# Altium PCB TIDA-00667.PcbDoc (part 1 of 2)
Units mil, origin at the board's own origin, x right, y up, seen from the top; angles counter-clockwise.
Board outline 4000 x 4000 mil, 6 copper layers (Top, Inner Layer 2, Inner Layer 3, Inner Layer 4, Inner Layer 5, Bottom), stack 58.1 mil thick; 114 components, 88 nets, 384 pads, 631 vias.
Unrouted connection lines stored in the file: 538.
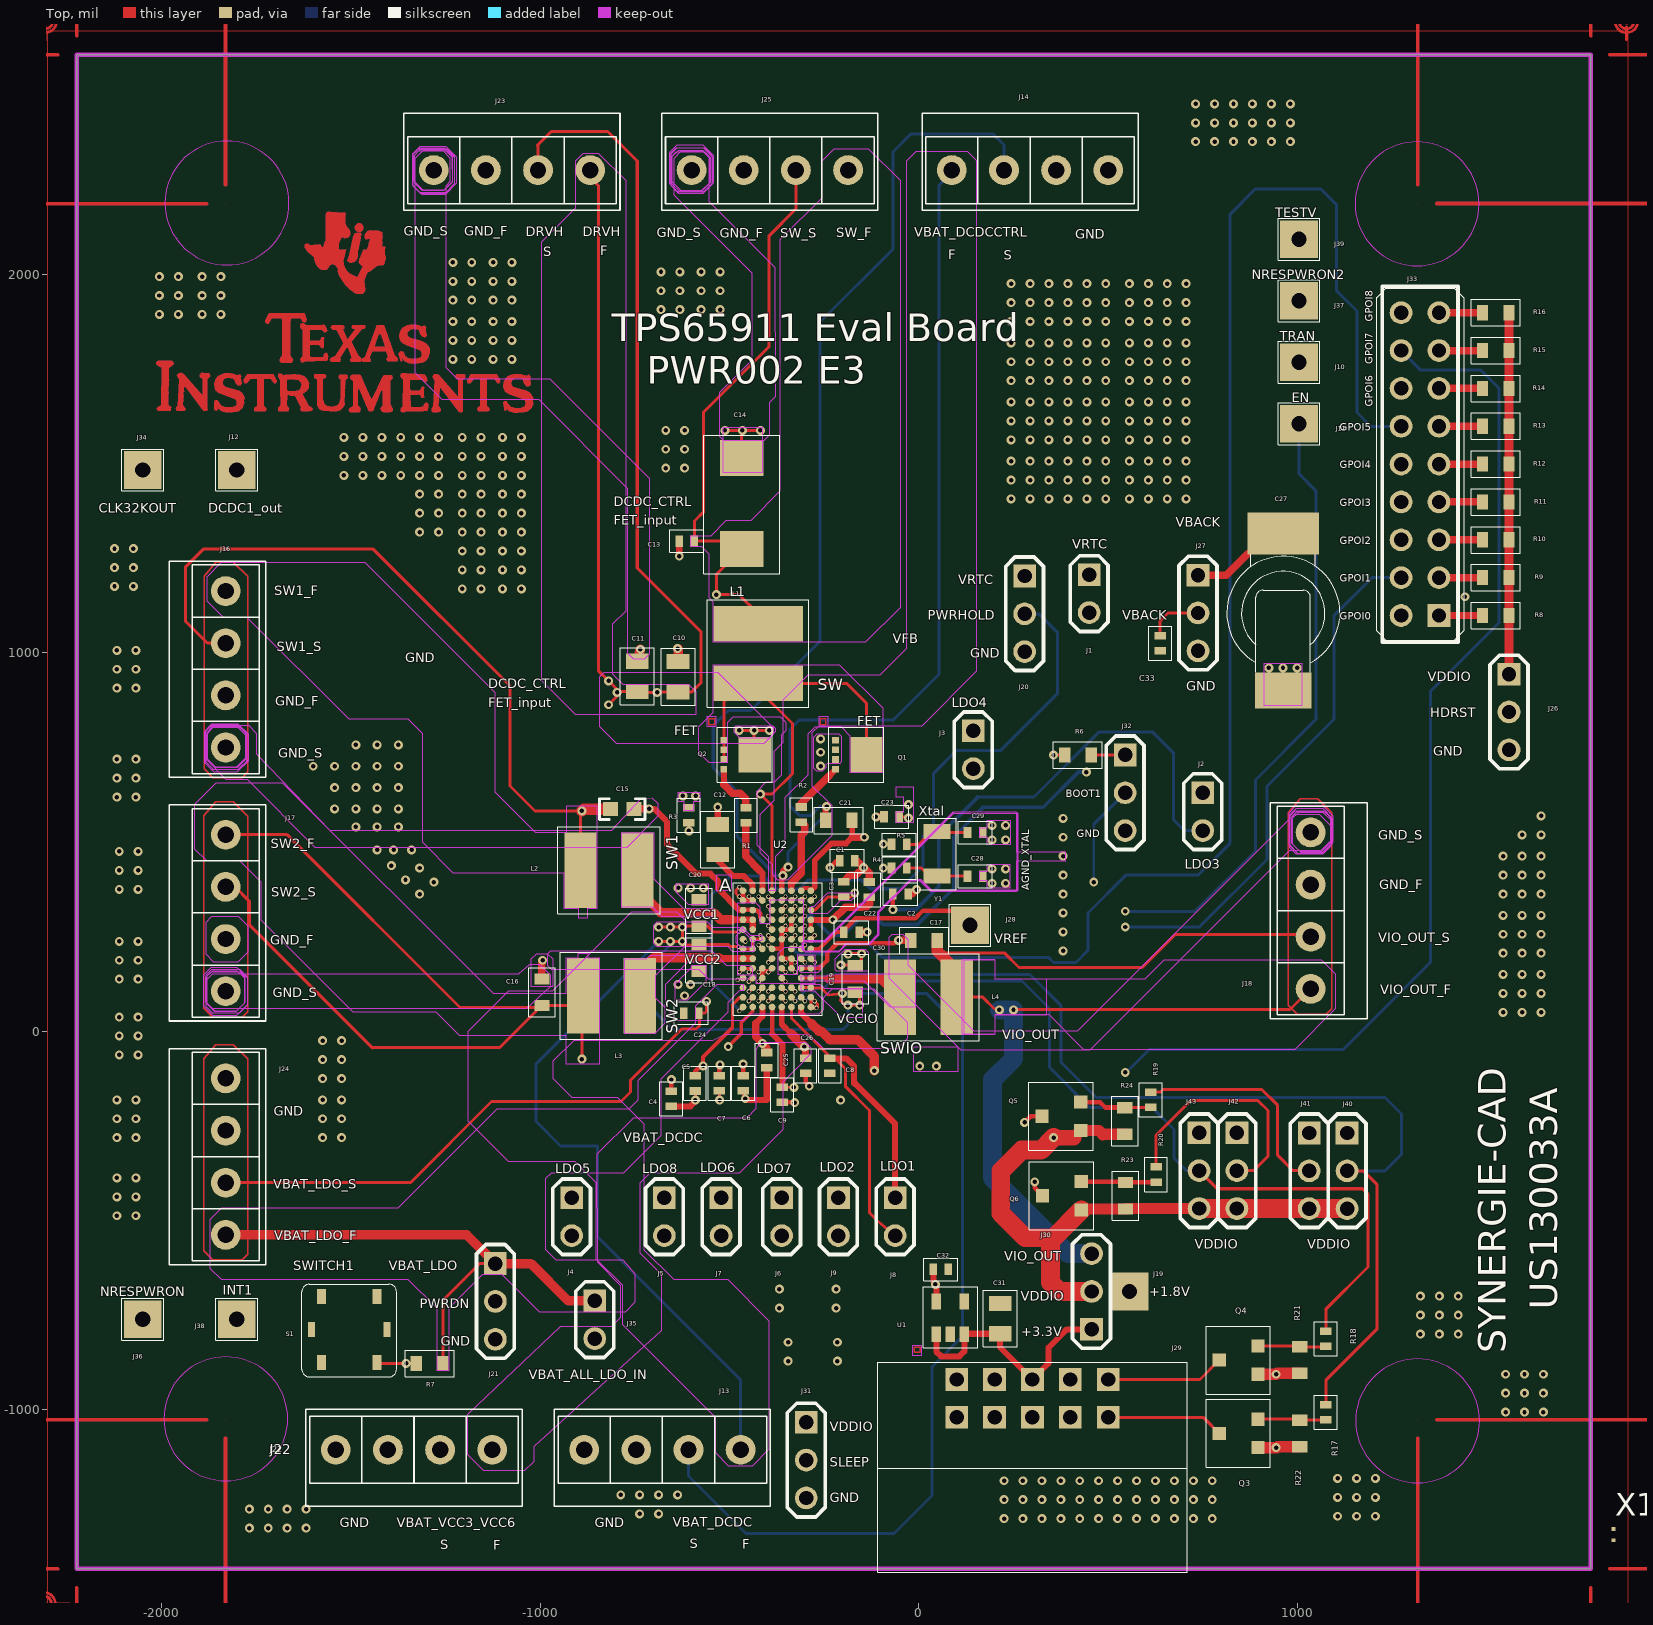
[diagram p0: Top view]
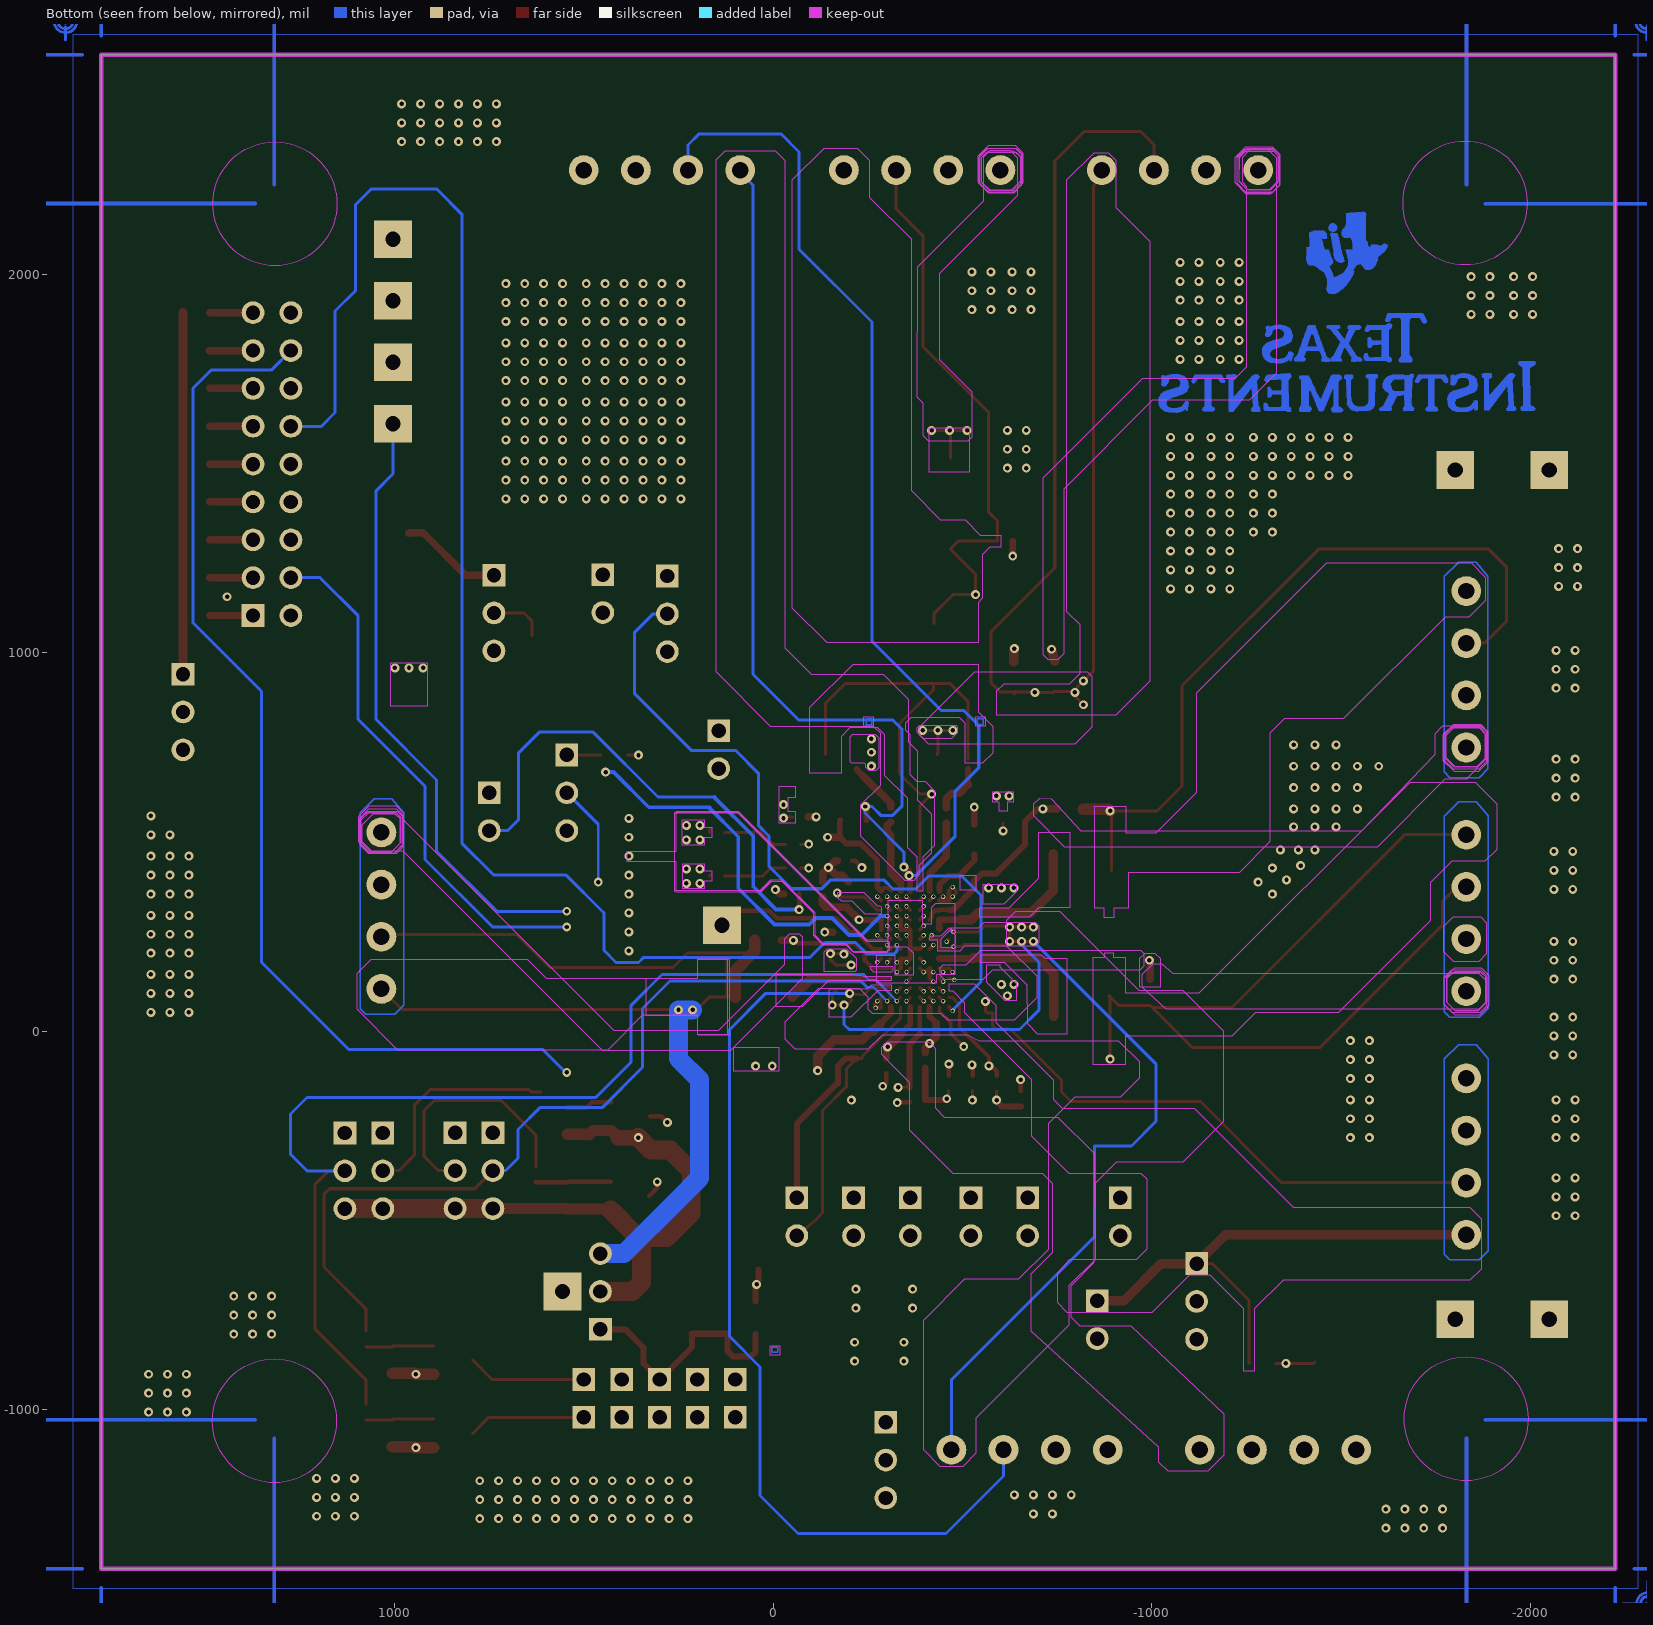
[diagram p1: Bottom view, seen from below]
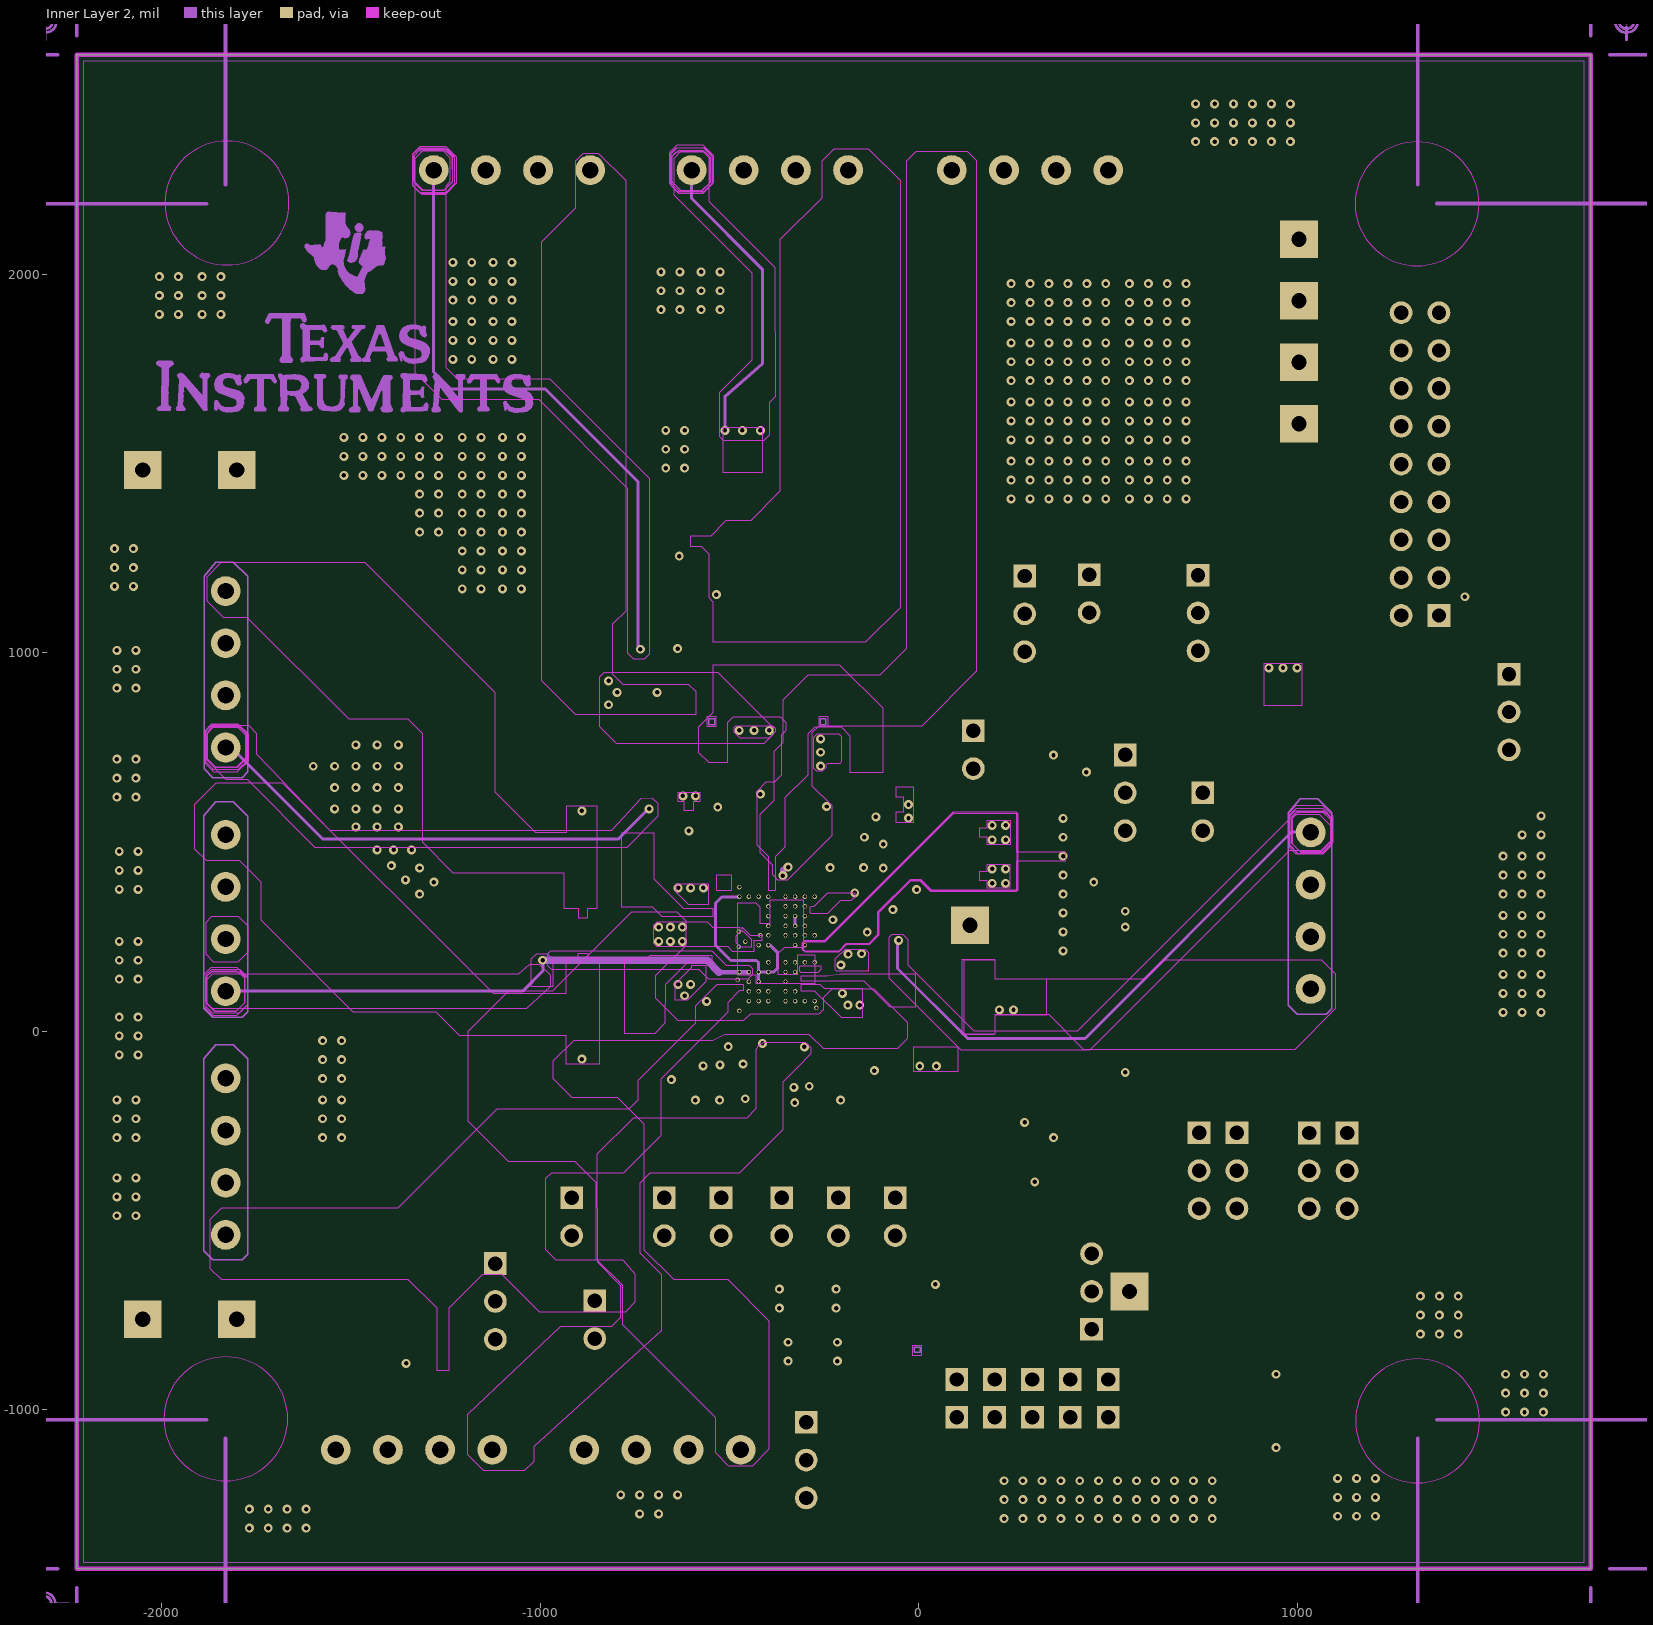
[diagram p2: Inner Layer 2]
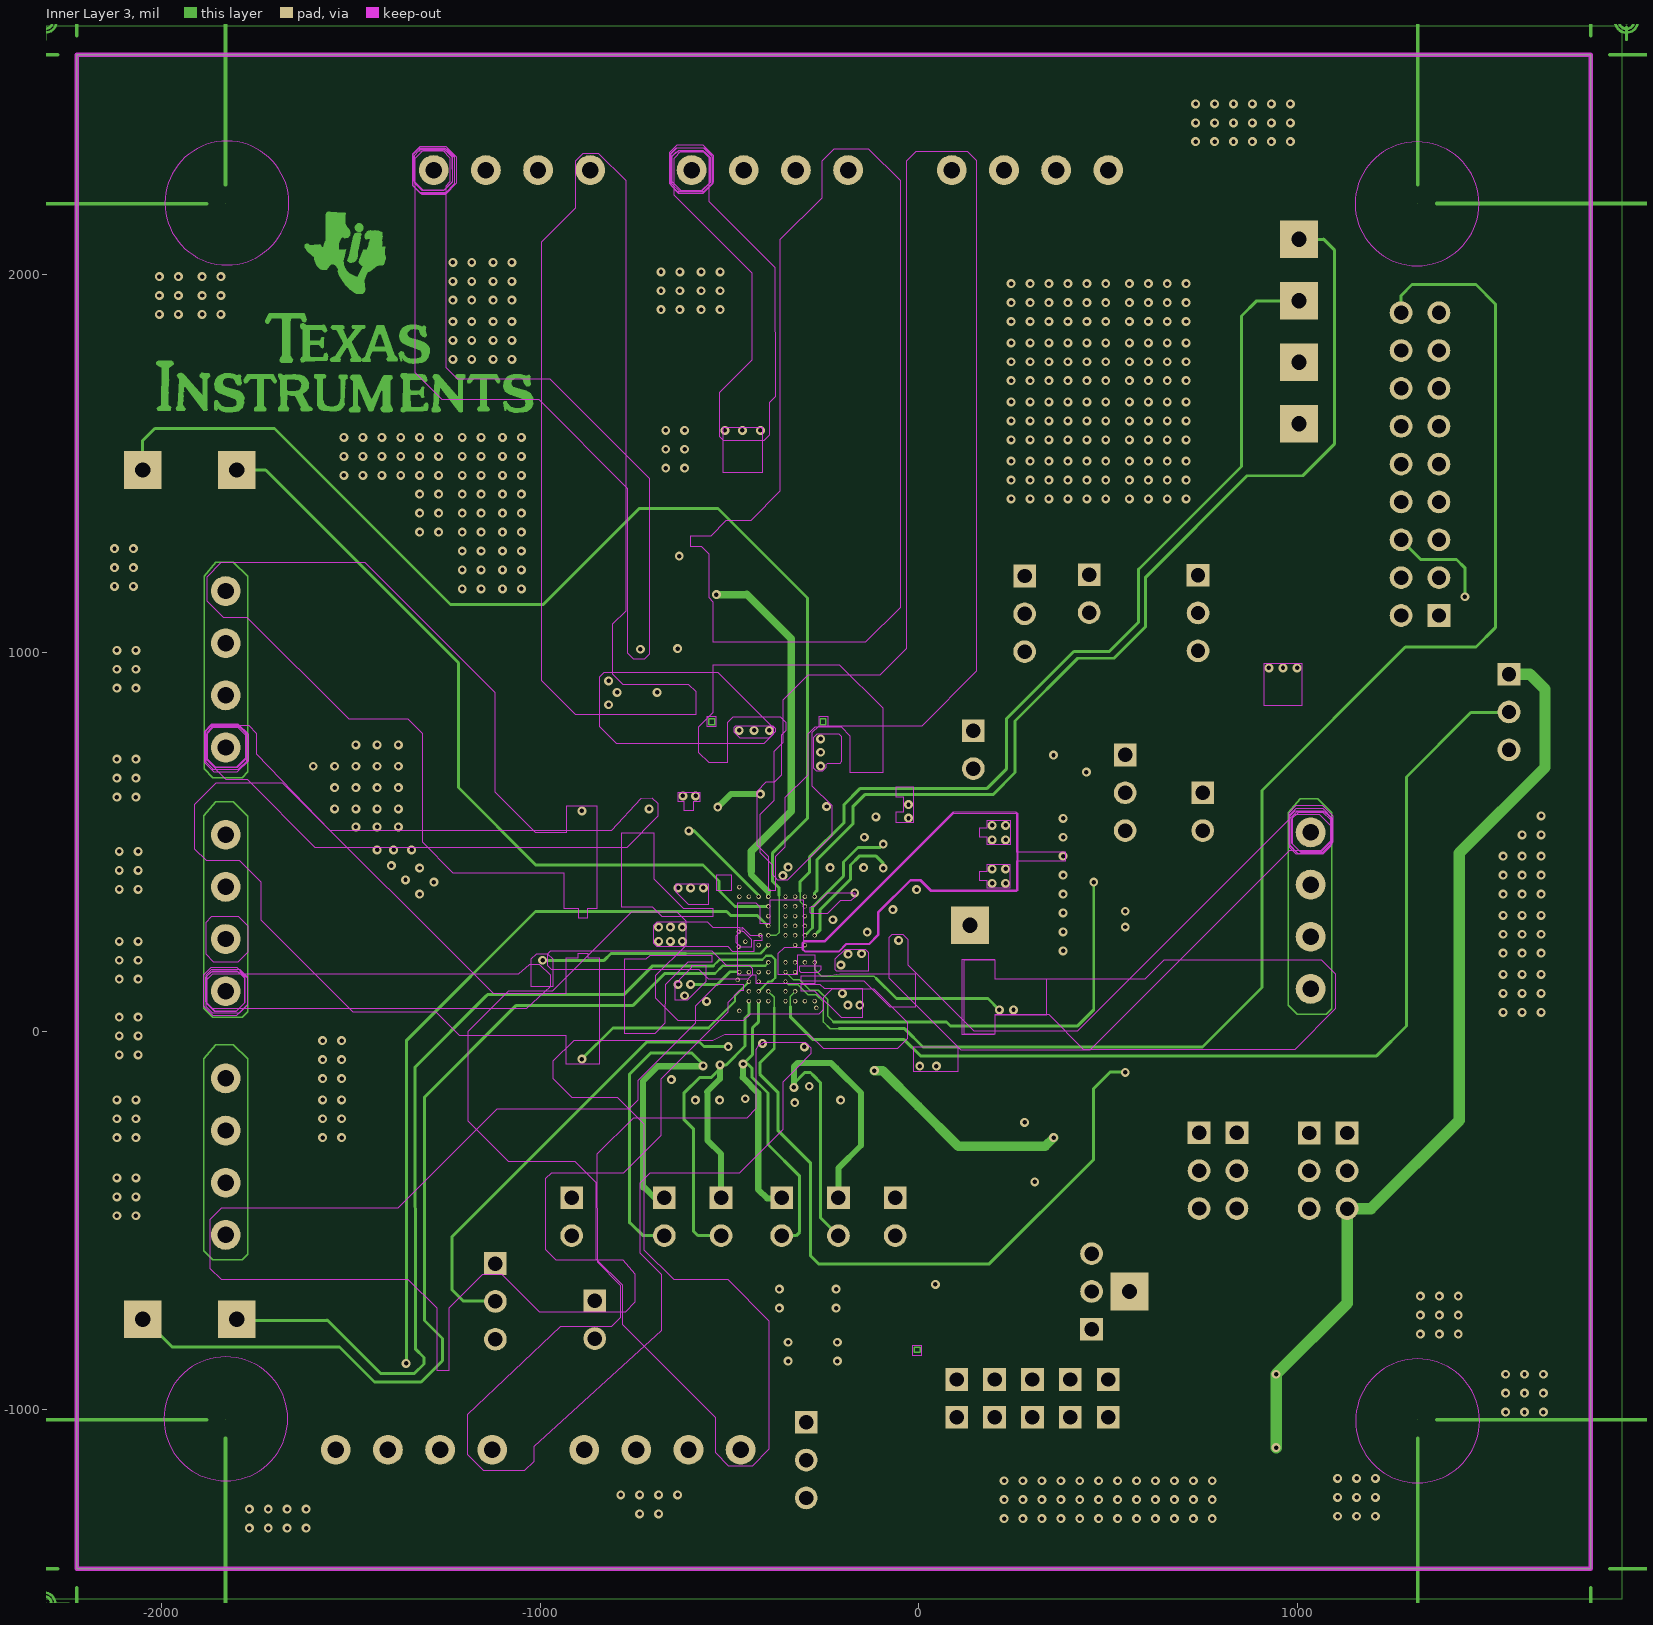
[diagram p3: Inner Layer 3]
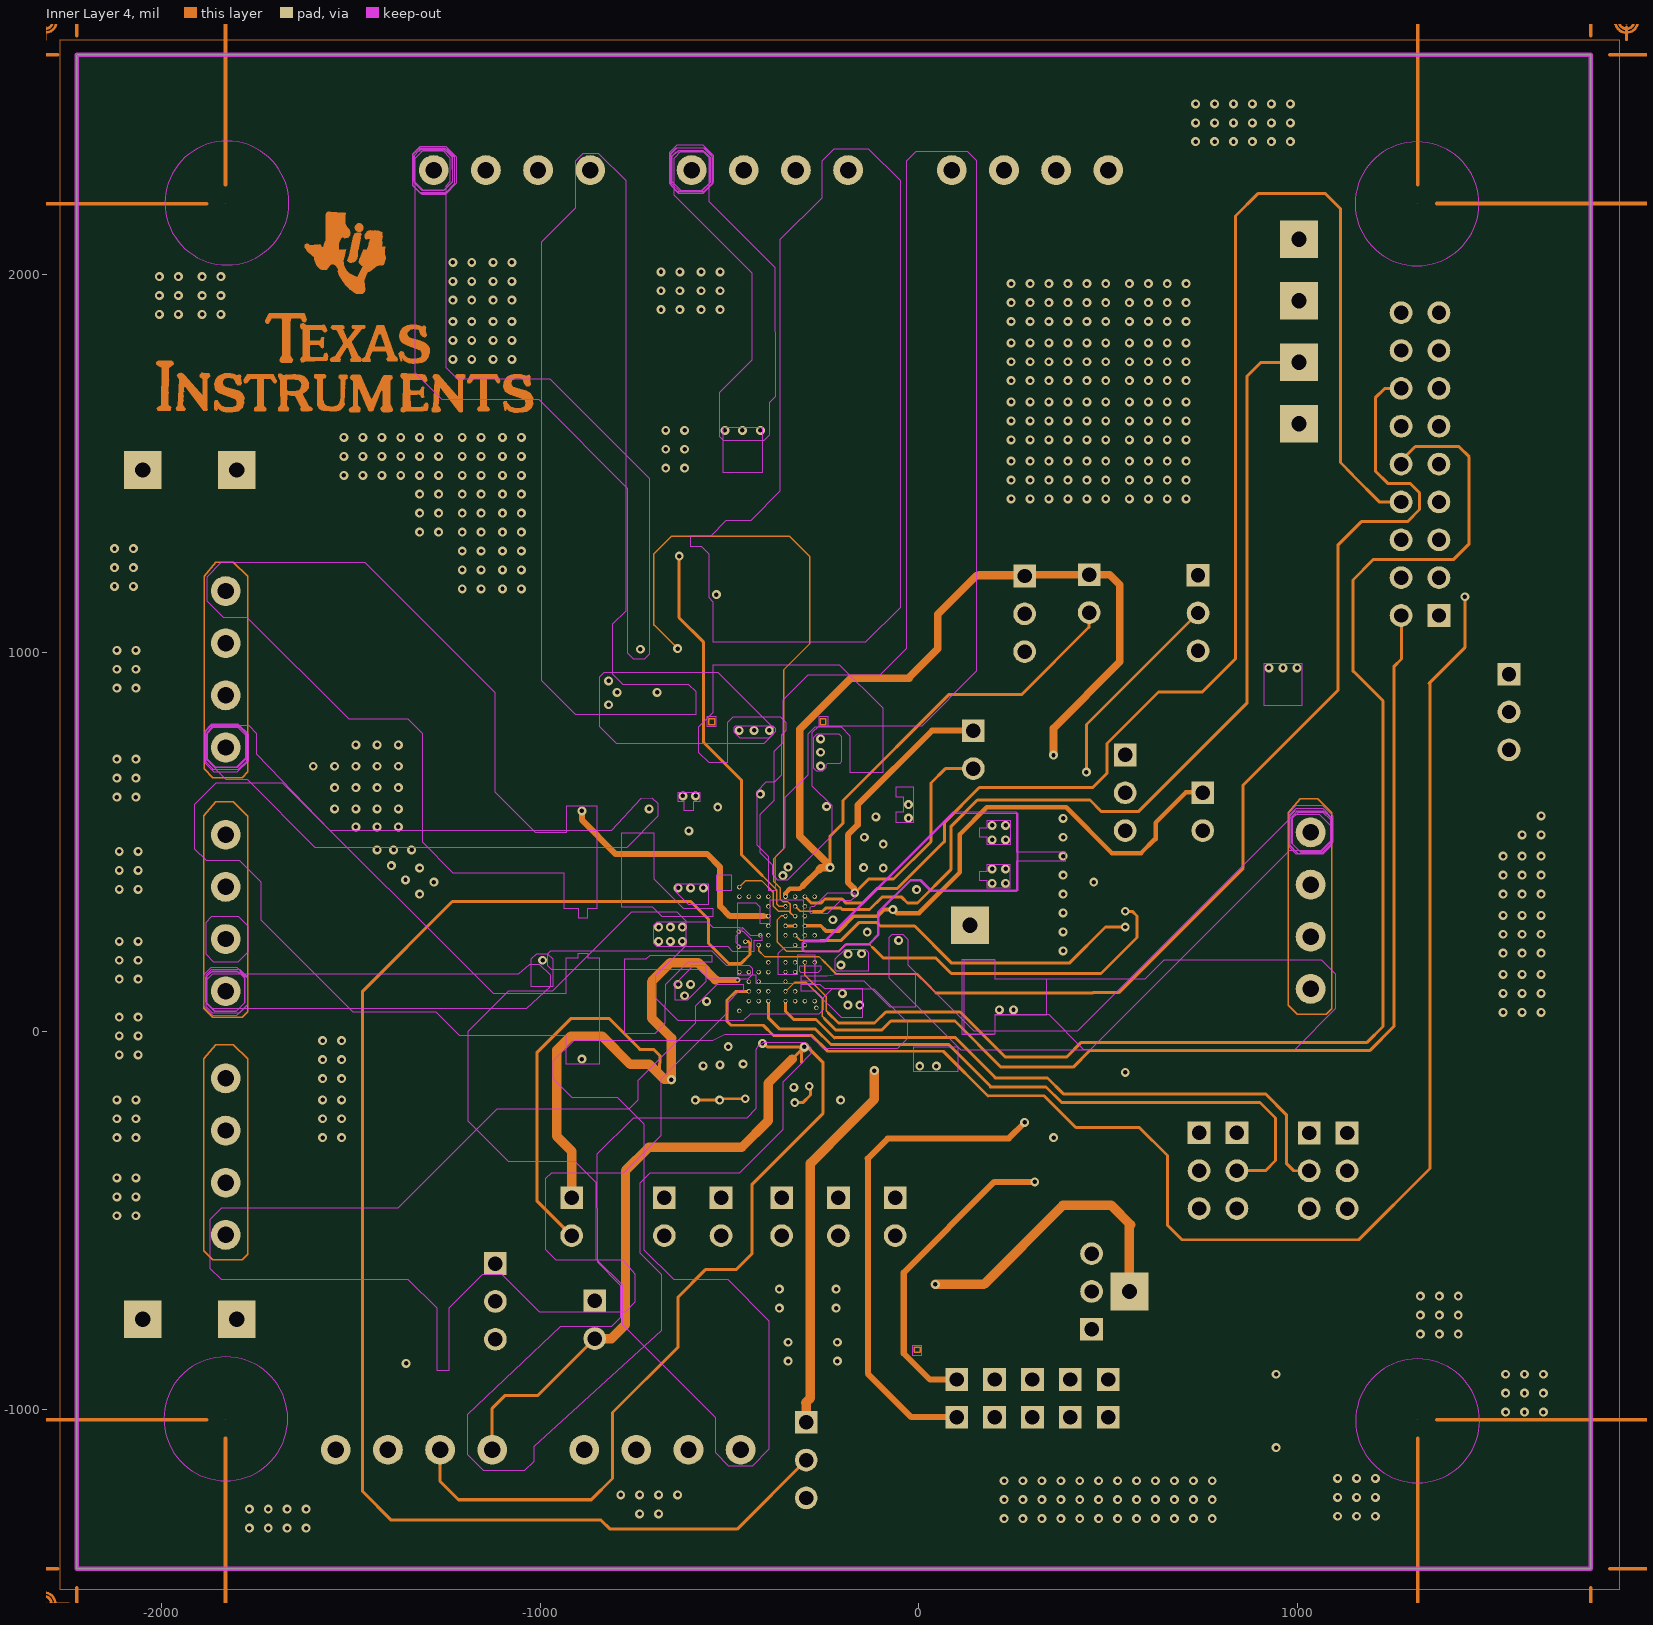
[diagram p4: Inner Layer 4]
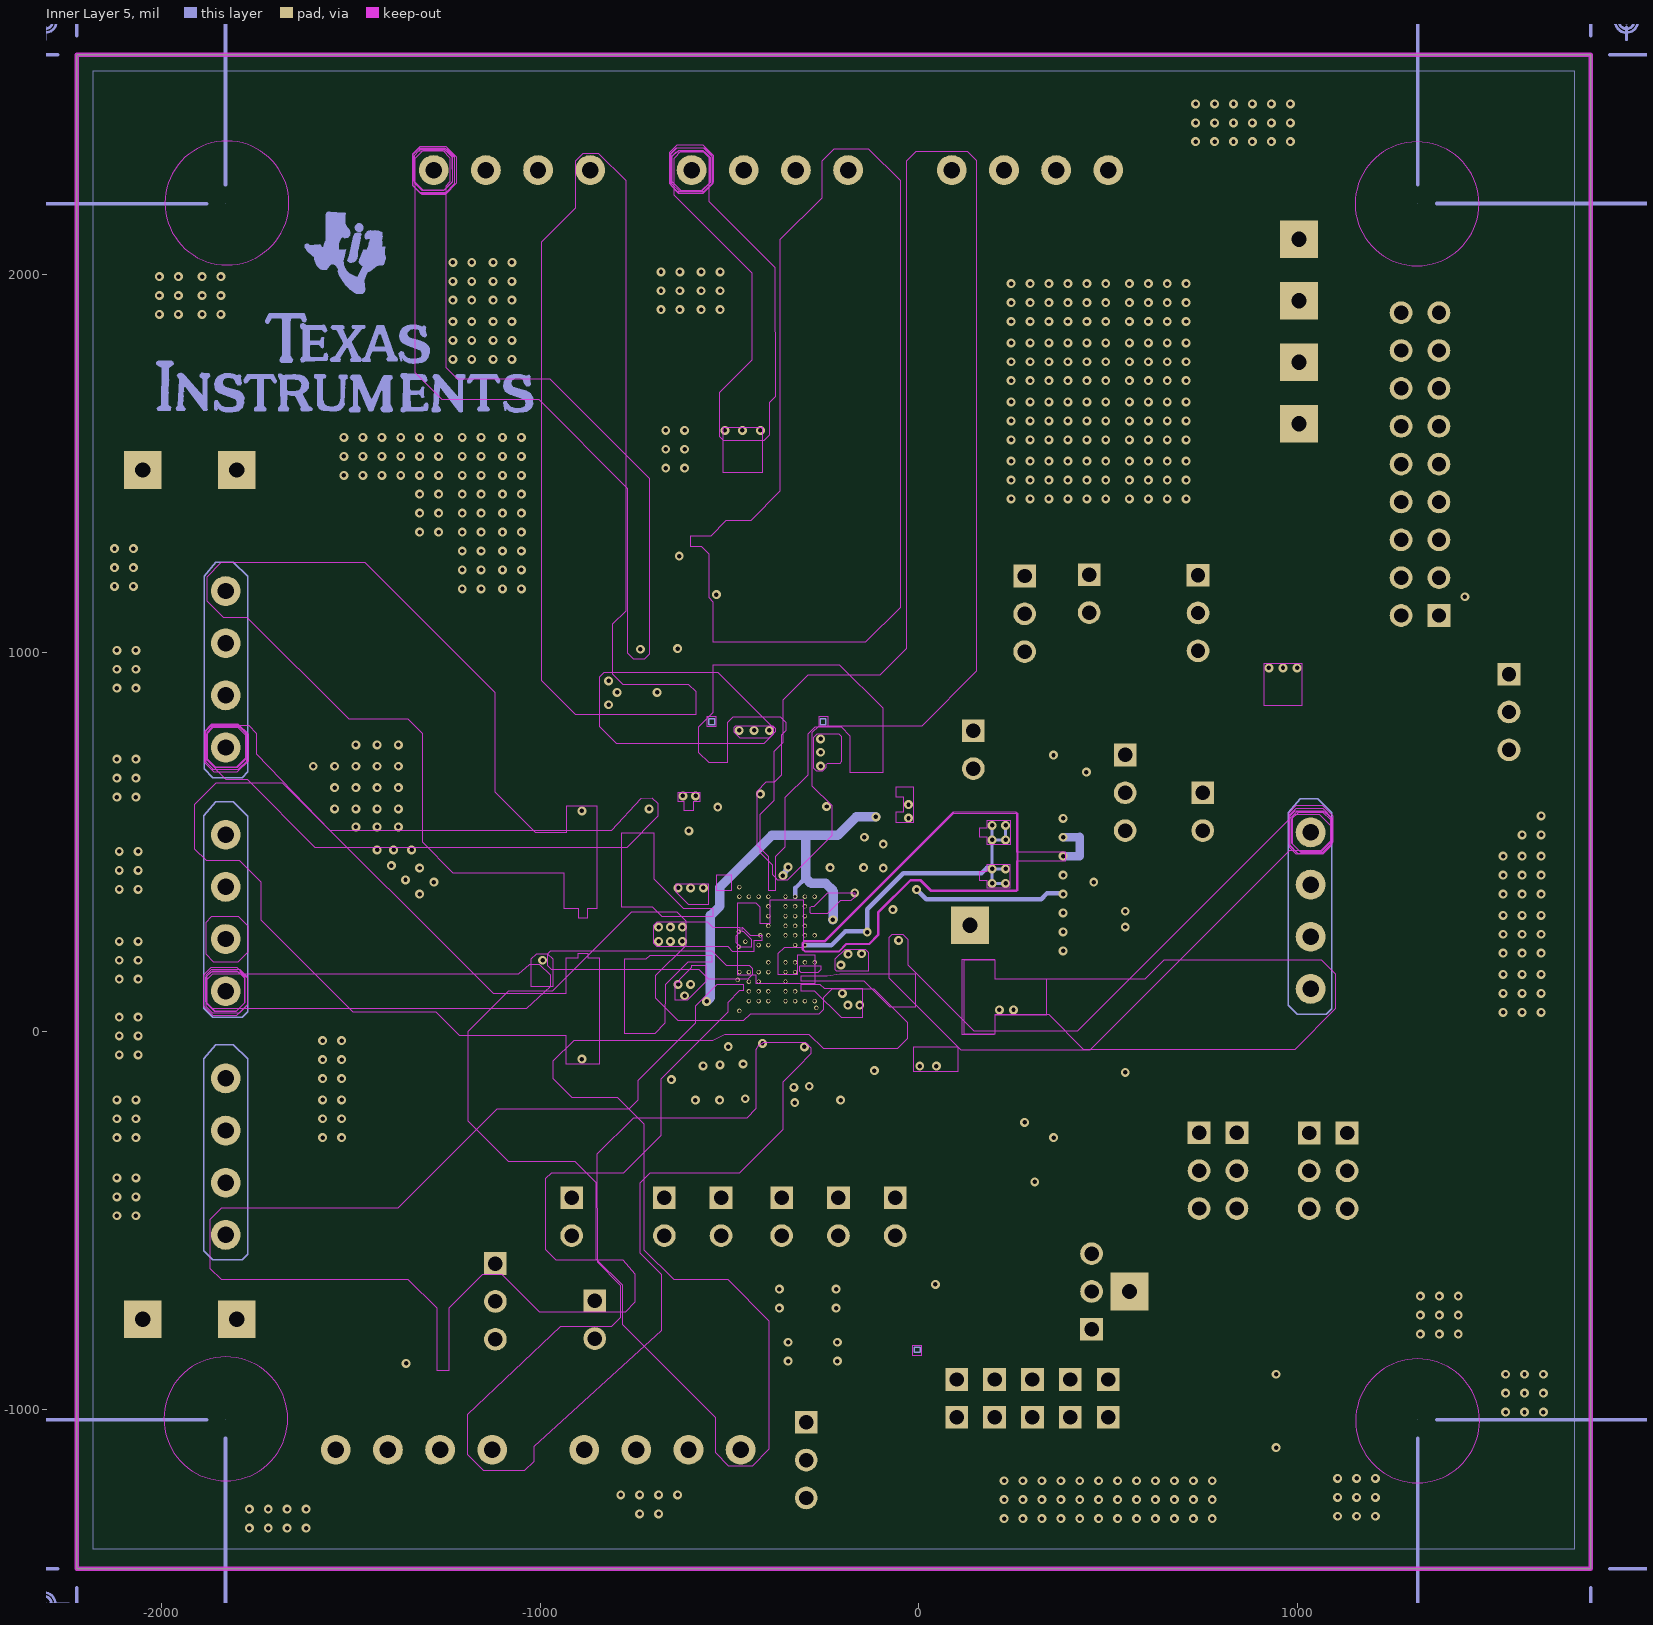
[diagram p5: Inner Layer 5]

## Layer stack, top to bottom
Solder Mask Top: solder mask 0.4, Solder Resist, Dk 3.5
Top: signal copper 1.35
Dielectric1: dielectric 10, FR-4, Dk 4.3
Inner Layer 2: signal copper 1.35
Dielectric2: dielectric 10, FR-4, Dk 4.3
Inner Layer 3: signal copper 1.35
Dielectric3: dielectric 10, FR-4, Dk 4.3
Inner Layer 4: signal copper 1.35
Dielectric4: dielectric 10, FR-4, Dk 4.3
Inner Layer 5: signal copper 1.35
Dielectric5: dielectric 10, FR-4, Dk 4.3
Bottom: signal copper 1.35
Solder Mask Bottom: solder mask 0.4, Solder Resist, Dk 3.5

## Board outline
-2225,-1420 1775,-1420 1775,2580 -2225,2580

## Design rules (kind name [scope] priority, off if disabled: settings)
Clearance [All] p1: gap=10
PlaneConnect "Power Plane Connect Style - pads with no thermal" [(Name='J29-1') Or (Name='J29-2') Or (Name='J29-3') Or (Name='J29-4') Or (Name='J29-7') Or (Name='J29-8') Or (Name='W1-1') Or (Name='W2-1') Or (Name='W3-1') Or (Name='W4-1')] p1: planeconnectstyle=NoConnect reliefexpansion=20 reliefentries=4 reliefconductorwidth=10 reliefairgap=10 // PAD - No Thermal Connect Rule
PlaneConnect [All] p2: planeconnectstyle=Relief reliefexpansion=20 reliefentries=4 reliefconductorwidth=10 reliefairgap=10
PolygonConnect [All] p1: connectstyle=Relief reliefconductorwidth=10 reliefentries=4 polygonreliefangle="90 Angle" airgapwidth=10
RoomDefinition SHEET2 [InComponentClass('SHEET2')] p1: confinementstyle=ConfineIn formatcopy=TRUE lockcomponents=FALSE outline 1820,-1355 1935,-1355 1935,-1205 1820,-1205
RoomDefinition SHEET1 [InComponentClass('SHEET1')] p2: confinementstyle=ConfineIn formatcopy=TRUE lockcomponents=FALSE outline -28000,-28000 -26000,-28000 -26000,-27000 -28000,-27000
RoutingVias [All] p1: holewidth=28 width=50 viastyle="Through Hole" minholewidth=28 minwidth=50 maxholewidth=28 maxwidth=50
SolderMaskExpansion [All] p1: expansion=4
UnpouredPolygon [All] p1: allowunpoured=FALSE
Width [All] p1: maxlimit=10 minlimit=10 preferedwidth=10
28 further rules are at their usual default settings.

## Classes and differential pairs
component class SHEET2: C28 C29 C30 C31 C32 J19 J20 J21 J26 J28 J29 J30 J31 J32 J33 J34 J36 J37 J38 J39 J40 J41 J42 J43 Q3 Q4 Q5 Q6 R4 R5 R6 R7 R8 R9 R10 R11 R12 R13 R14 R15 R16 R17 R18 R19 R20 R21 R22 R23 R24 S1 U1 X1 Y1
component class SHEET1: C1 C2 C3 C4 C5 C6 C7 C8 C9 C10 C11 C12 C13 C14 C15 C16 C17 C18 C19 C20 C21 C22 C23 C24 C25 C26 C27 C33 J1 J2 J3 J4 J5 J6 J7 J8 J9 J10 J11 J12 J13 J14 J16 J17 J18 J22 J23 J24 J25 J27 J35 L1 L2 L3 L4 Q1 Q2 R1 R2 R3 U2

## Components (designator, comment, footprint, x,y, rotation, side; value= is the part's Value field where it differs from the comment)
C1 "C0402" 0402 -189.39,450.18 r0 top
C2 "C0402" 0402 -48.55,362.55 r0 top
C3 "C0402" 0402 -198.79,374.98 r90 top
C4 "C0402" 0402 -654.22,-178.63 r270 top
C5 "C0402" 0402 -591.12,-137.96 r270 top
C6 "C0402" 0402 -463.87,-137.18 r270 top
C7 "C0402" 0402 -526.96,-137.18 r270 top
C8 "C0402" 0402 -235,-91.52 r270 top
C9 "C0402" 0402 -360.72,-167.94 r270 top
C10 "C0805" C0805 -636.21,936.46 r270 top
C11 "C0805" C0805 -743.75,937.5 r270 top
C12 "C0805" C0805 -531.34,506.47 r270 top
C13 "C0402" 0402 -612.89,1294.84 r180 top
C14 "CAP_EEF-CD" CAP_POSCAP_D -467.98,1393.92 r90 top
C15 "GRM188R60J226MEA0J" 0603 -783.62,586.75 r180 top
C16 "C0603" C603 -996,103 r270 top
C17 "C0603" C603 13.99,240.01 r0 top
C18 "C0603" C603 -581.25,193.75 r90 top
C19 "C0603" C603 -168,138 r270 top
C20 "C0603" C603 -581.25,312.5 r270 top
C21 "C0603" C603 -211.46,557.28 r180 top
C22 "C0402" 0402 -131.27,374.25 r90 top
C23 "C0402" 0402 -72.19,566.47 r0 top
C24 "C0402" 0402 -601.46,47.84 r180 top
C25 "C0402" 0402 -401.93,-76.23 r270 top
C26 "C0402" 0402 -299.14,-91.12 r270 top
C27 "CAP_EECEN0F204AK" CAP_PAN_AK_CODE 962.5,1105 r0 top
C28 "C0402" 0402 148.52,409.72 r0 top
C29 "C0402" 0402 148.52,524.88 r0 top
C30 "C0402" 0402 -177.97,261.32 r180 top
C31 "C0805" C0805 214.95,-759.13 r90 top
C32 "C0402" 0402 58.19,-629.09 r180 top
C33 "C0402" 0402 637.5,1025 r90 top
J1 "HEADER_1X2" HDR100_1X2 450,1206 r270 top
J2 "HEADER_1X2" HDR100_1X2 750,630.03 r270 top
J3 "HEADER_1X2" HDR100_1X2 143.75,793.75 r270 top
J4 "HEADER_1X2" HDR100_1X2 -917.18,-440 r270 top
J5 "HEADER_1X2" HDR100_1X2 -672.5,-440 r270 top
J6 "HEADER_1X2" HDR100_1X2 -362.5,-440 r270 top
J7 "HEADER_1X2" HDR100_1X2 -522.5,-440 r270 top
J8 "HEADER_1X2" HDR100_1X2 -62.5,-440 r270 top
J9 "HEADER_1X2" HDR100_1X2 -212.5,-440 r270 top
J10 "HEADER_1X1" TH-040 1003.8,1767.28 r270 top
J11 "HEADER_1X1" TH-040 1003.8,1604.78 r270 top
J12 "HEADER_1X1" TH-040 -1802.04,1482.46 r270 top
J13 "CON4" ED555-3.5-4P -677.54,-1105.57 r0 top
J14 "CON4" ED555-3.5-4P 293.75,2275 r180 top
J16 "CON4" ED555-3.5-4P -1831.25,956.25 r270 top
J17 "CON4" ED555-3.5-4P -1831.25,312.5 r270 top
J18 "CON4" ED555-3.5-4P 1035.02,318.6 r90 top
J19 "HEADER_1X1" TH-040 556.25,-687.5 r0 top
J20 "HEADER_1X3" HDR100_1X3#1 279.4,1202.8 r270 top
J21 "HEADER_1X3" HDR100_1X3#1 -1118.75,-613.75 r270 top
J22 "CON4" ED555-3.5-4P -1333.79,-1105.57 r0 top
J23 "CON4" ED555-3.5-4P -1075,2275 r180 top
J24 "CON4" ED555-3.5-4P -1831.25,-331.25 r270 top
J25 "CON4" ED555-3.5-4P -393.75,2275 r180 top
J26 "HEADER_1X3" HDR100_1X3#1 1559.03,943.44 r270 top
J27 "HEADER_1X3" HDR100_1X3#1 737.5,1205 r270 top
J28 "HEADER_1X1" TH-040 135,280 r270 top
J29 "CONN_2510-5002UB" CONN_2X5-R 500,-920 r180 top
J30 "HEADER_1X3" HDR100_1X3#1 456.25,-787.5 r90 top
J31 "HEADER_1X3" HDR100_1X3#1 -297.57,-1032.96 r270 top
J32 "HEADER_1X3" HDR100_1X3#1 545,730 r270 top
J33 "HEADER_2X9" HEADER_2X9 1374,1098.3 r90 top
J34 "HEADER_1X1" TH-040 -2050.51,1482.46 r270 top
J35 "HEADER_1X2" HDR100_1X2 -856.25,-712 r270 top
J36 "HEADER_1X1" TH-040 -2050.51,-761.03 r270 top
J37 "HEADER_1X1" TH-040 1003.8,1929.78 r270 top
J38 "HEADER_1X1" TH-040 -1802.04,-761.03 r270 top
J39 "HEADER_1X1" TH-040 1003.8,2092.28 r270 top
J40 "HEADER_1X3" HDR100_1X3#2 1131.25,-268.75 r270 top
J41 "HEADER_1X3" HDR100_1X3#2 1031.25,-268.75 r270 top
J42 "HEADER_1X3" HDR100_1X3#1 840.27,-268.32 r270 top
J43 "HEADER_1X3" HDR100_1X3#1 740.27,-268.32 r270 top
L1 "IND_XAL6030_SERIES" IND_6X6_MM -424.56,998.01 r90 top
L2 "IND_VLCF5020T-SERIES" IND_VLCF5020T -818.75,425 r180 top
L3 "IND_VLCF5020T-SERIES" IND_VLCF5020T -812.5,93.75 r180 top
L4 "IND_VLCF5020T-SERIES" IND_VLCF5020T 25,90 r0 top
Q1 "TR-FDMC7660" MO-240 -165,730.51 r270 top
Q2 "TR-FDMC7660" MO-240 -460.16,730.51 r270 top
Q3 "TR-BSS138" SOT-23 843.75,-1062.5 r90 top
Q4 "TR-BSS138" SOT-23 843.75,-868.75 r90 top
Q5 "TR-BSS138" SOT-23 375.24,-224.63 r90 top
Q6 "TR-BSS138" SOT-23 376.68,-434.76 r90 top
R1 "R0402" 0402 -456.78,570.58 r90 top
R2 "R0402" 0402 -310.31,572.4 r90 top
R3 "R0402" 0402 -607.76,570.58 r90 top
R4 "R0402" 0402 -52.2,431.21 r180 top
R5 "R0402" 0402 -52.2,493.71 r180 top
R6 "R0603_5%" R603#1 420,730 r0 top
R7 "R0603_5%" R603#1 -1292.47,-877.63 r180 top
R8 "R0603_5%" R603#1 1524,1098.3 r180 top
R9 "R0603_5%" R603#1 1524,1198.3 r180 top
R10 "R0603_5%" R603#1 1524,1298.3 r180 top
R11 "R0603_5%" R603#1 1524,1398.3 r180 top
R12 "R0603_5%" R603#1 1524,1498.3 r180 top
R13 "R0603_5%" R603#1 1524,1598.3 r180 top
R14 "R0603_5%" R603#1 1524,1698.3 r180 top
R15 "R0603_5%" R603#1 1524,1798.3 r180 top
R16 "R0603_5%" R603#1 1524,1898.3 r180 top
R17 "R0402" 0402 1075,-1006.25 r270 top
R18 "R0402" 0402 1075,-812.5 r270 top
R19 "R0402" 0402 612.74,-180.88 r270 top
R20 "R0402" 0402 626.68,-378.51 r270 top
R21 "R0603_5%" R603#2 1006.25,-868.75 r270 top
R22 "R0603_5%" R603#2 1006.25,-1062.5 r270 top
R23 "R0603_5%" R603#1 545.43,-434.76 r270 top
R24 "R0603_5%" R603#1 543.99,-237.13 r270 top
S1 "SW_EVQ-PLHA15" SW_EVQPL -1504.97,-790.13 r90 top
U1 "TPS76318DBV" SOT23-5P 83.13,-755.57 r90 top
U2 "TPS65911XZRC_ALT" ZRC-98 -375,217.5 r270 top
X1 "SHORT" WIRE 1835,-1315 r0 top
Y1 "CRYSTAL_FC-135" CRYSTAL-FC-135 47.8,468.71 r270 top

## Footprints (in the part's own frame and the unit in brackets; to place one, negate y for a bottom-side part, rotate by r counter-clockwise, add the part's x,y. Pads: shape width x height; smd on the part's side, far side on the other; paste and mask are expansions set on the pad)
0402 [mil]
  rect 20x30 smd mask+2: 1(-20,0) 2(20,0)
  silkscreen extent -45,-30 45,30
0603 [mm] "0603 from SM-752 data"
  rect 1x0.95 smd: 1(-0.8,0) 2(0.8,0)
  silkscreen extent -1.52,-0.69 1.52,0.69, body extent -0.87,-0.47 0.87,0.47, height 0.85
C603 [mil]
  rect 30x40 smd mask+4: 1(-35,0) 2(35,0)
  silkscreen extent -65,-35 65,35
C0805 [mil]
  rect 40x60 smd mask+2: 1(-40,0) 2(40,0)
  silkscreen extent -75,-45 75,45
CAP_PAN_AK_CODE [mm]
  rect 4.8x2.8 smd paste+0 mask+0.064: 1(0,5.34)
  rect 3.8x2.4 smd paste+0 mask+0.127: 2(0,-5.2)
  silkscreen extent -3.79,-3.98 3.81,3.94
CAP_POSCAP_D [mil]
  rect 95x115 smd mask+2.5: 1(-120,0) 2(120,0)
  silkscreen extent -185,-100 180,100
CONN_2X5-R [mil]
  rect 60x60 hole 38: 1(0,0) 2(0,100) 3(100,0) 4(100,100) 5(200,0) 6(200,100) 7(300,0) 8(300,100) 9(400,0) 10(400,100)
  silkscreen extent -209,-46 609,510
CRYSTAL-FC-135 [mm]
  rect 1x1.8 smd mask+0.052: 1(-1.5,0) 2(1.5,0)
  silkscreen extent -2.4,-1.3 2.4,1.3
ED555-3.5-4P [mm]
  round 2 hole 1.1 mask+0.1: 1(-5.25,0) 2(-1.75,0) 3(1.75,0) 4(5.25,0)
  silkscreen extent -7.25,-3.8 7.25,2.7
HDR100_1X2 [mil]
  rect 60x60 hole 38: 1(0,0)
  round 60 hole 38: 2(100,0)
  silkscreen extent -50,-50 150,50
HDR100_1X3#1 [mil]
  rect 60x60 hole 38: 1(0,0)
  round 60 hole 38: 2(100,0) 3(200,0)
  silkscreen extent -50,-50 250,50
HDR100_1X3#2 [mil]
  rect 60x60 hole 38: 1(0,0)
  round 60 hole 38 mask+2.5: 2(100,0) 3(200,0)
  silkscreen extent -50,-50 250,50
HEADER_2X9 [mil]
  rect 60x60 hole 38: 1(0,0)
  round 60 hole 38: 2(0,100) 3(100,0) 4(100,100) 5(200,0) 6(200,100) 7(300,0) 8(300,100) 9(400,0) 10(400,100) 11(500,0) 12(500,100) 13(600,0) 14(600,100) 15(700,0) 16(700,100) 17(800,0) 18(800,100)
  silkscreen extent -70,-65 870,165
IND_6X6_MM [mm]
  rect 2.4x6 smd paste+0 mask+0.063: 1(-2,0) 2(2,0)
  silkscreen extent -3.61,-3.4 3.59,3.4
IND_VLCF5020T [mil]
  rect 85x200 smd mask+2.5: 1(-75,0) 2(75,0)
  silkscreen extent -135,-115 135,115
MO-240 [mm]
  rect 0.45x0.45 smd mask+0.025: 1(-0.975,-1.4) 2(-0.325,-1.4) 3(0.325,-1.4) 4(0.975,-1.4)
  rect 2.4x2.15 smd mask+0.025: 5(0,0.675)
  Keep-Out Layer region: -1.905,-1.905 -2.54,-1.905 -2.54,-2.54 -1.905,-2.54 -1.905,-1.905
  silkscreen extent -1.85,-1.85 1.85,1.85
R603#1 [mil]
  rect 30x40 smd mask+2.5: 1(-35,0) 2(35,0)
  silkscreen extent -65,-35 65,35
R603#2 [mil]
  rect 30x40 smd: 1(-35,0) 2(35,0)
SOT23-5P [mil]
  rect 42x25 smd mask+2.5: 1(-45,37) 2(-45,0) 3(-45,-37) 4(42,-37) 5(42,37)
  Keep-Out Layer region: -100,75 -75,75 -75,100 -100,100 -100,75
  silkscreen extent -80,-73 80,72
SOT-23 [mil]
  rect 35x35 smd mask+2.5: 1(-37.5,-52.5) 2(37.5,-52.5) 3(0,50)
  silkscreen extent -90,-85 90,85
SW_EVQPL [mil]
  rect 40x24 smd mask+2.5: A(-85,73) A'(89,73) B(-85,-73) B'(89,-73)
  rect 40x18 smd mask+2.5: M1(2,-99.5) M2(2,99.5)
  silkscreen extent -123,-125 122,125
TH-040 [mil]
  rect 100x100 hole 40: 1(0,0)
  silkscreen extent -55,-55 55,55
WIRE [mil]
  rect 10x10 smd mask-5: 1(0,0) 2(0,-30)
ZRC-98 [mm]
  round 0.45 smd: A1(-3.9,-2.275) A2(-3.9,-1.625) A3(-3.9,-0.975) A4(-3.9,-0.325) A5(-3.9,0.325) A6(-3.9,0.975) A7(-3.9,1.625) A8(-3.9,2.275) B1(-3.25,-2.275) B2(-3.25,-1.625) B3(-3.25,-0.975) B4(-3.25,-0.325) B5(-3.25,0.325) B6(-3.25,0.975) B7(-3.25,1.625) B8(-3.25,2.275) C1(-2.6,-2.275) C2(-2.6,-1.625) C4(-2.6,-0.325) C5(-2.6,0.325) C6(-2.6,0.975) C7(-2.6,1.625) C8(-2.6,2.275) D1(-1.95,-2.275) D2(-1.95,-1.625) D3(-1.95,-0.975) D4(-1.95,-0.325) D5(-1.95,0.325) D6(-1.95,0.975) D7(-1.95,1.625) D8(-1.95,2.275) E1(-1.3,-2.275) E2(-1.3,-1.625) E4(-1.3,-0.325) E5(-1.3,0.325) E6(-1.3,0.975) E7(-1.3,1.625) E8(-1.3,2.275) F1(-0.65,-2.275) F2(-0.65,-1.625) F3(-0.65,-0.975) F4(-0.65,-0.325) F5(-0.65,0.325) F6(-0.65,0.975) F7(-0.65,1.625) F8(-0.65,2.275) G1(0,-2.275) G2(0,-1.625) G3(0,-0.975) G4(0,-0.325) G6(0,0.975) G7(0,1.625) G8(0,2.275) H1(0.65,-2.275) H2(0.65,-1.625) H4(0.65,-0.325) H5(0.65,0.325) H6(0.65,0.975) H7(0.65,1.625) H8(0.65,2.275) J1(1.3,-2.275) J2(1.3,-1.625) J3(1.3,-0.975) J4(1.3,-0.325) J5(1.3,0.325) J6(1.3,0.975) J7(1.3,1.625) J8(1.3,2.275) K1(1.95,-2.275) K2(1.95,-1.625) K3(1.95,-0.975) K5(1.95,0.325) K7(1.95,1.625) K8(1.95,2.275) L1(2.6,-2.275) L2(2.6,-1.625) L3(2.6,-0.975) L4(2.6,-0.325) L5(2.6,0.325) L6(2.6,0.975) L7(2.6,1.625) L8(2.6,2.275) M1(3.25,-2.275) M2(3.25,-1.625) M3(3.25,-0.975) M4(3.25,-0.325) M5(3.25,0.325) M6(3.25,0.975) M7(3.25,1.625) M8(3.25,2.275) N1(3.9,-2.275) N2(3.9,-1.625) N3(3.9,-0.975) N4(3.9,-0.325) N5(3.9,0.325) N6(3.9,0.975) N7(3.9,1.625) N8(3.9,2.275)
  Keep-Out Layer region: -4.955,-3.047 -4.955,-4.063 -3.939,-4.063 -3.939,-3.047 -4.955,-3.047
  silkscreen extent -4.45,-2.92 4.45,3.05

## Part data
C1 C2 C3 C4 C5 C6 C7 C8 C9 C10 C11 C12 C13 C22 C23 C24 C25 C26 C28 C29 C30 C31 C32 C33: "Capacitor, Ceramic, vvV, [temp],  [tol]"
C14: "Capacitor, Aluminum, 350V, 20%"
C15: "CAP, CERM, 22 µF, 6.3 V, +/- 20%, X5R, 0603"
C16 C17 C18 C19 C20 C21: "Capacitor, Ceramic, Low Inductance, vvV, [temp], [tol]"
C27: "Capacitor, Electric Double Layer"
J1 J2 J3 J4 J5 J6 J7 J8 J9 J35: "Header, Male 2-pin, 100mil spacing,"
J10 J11 J12 J19 J28 J34 J36 J37 J38 J39: "Through Hole,  O.040 Dia"
J13 J14 J16 J17 J18 J22 J23 J24 J25: "TERMINAL BLOCK 3.5MM 4POS PCB"
J20 J21 J26 J27 J30 J31 J32 J40 J41 J42 J43: "Header, Male 3-pin, 100mil spacing,"
J29: "Connector, Male Right Angle 2x5 pin, 100mil spacing, 4 Wall"
J33: "Header, Male 2x9 pin, 100mil spacing"
L1: "Inductor, Power, xx A, ±20%"
L2 L3 L4: "Inductor, SMT, yyA, zzmilliohm"
Q1 Q2: "MOSFET, NCh 30V, 20A, 2.2 millohm"
Q3 Q4 Q5 Q6: "MOSFET, Nch, 50V, 0.22A, 3.5 Ohm"
R1 R2 R3 R4 R5 R17 R18 R19 R20: "Resistor, Chip, 1/16W, x%"
R6 R7 R8 R9 R10 R11 R12 R13 R14 R15 R16 R21 R22 R23 R24: "Resistor, Chip, 1/16W, 5%"
S1: "Switch, 1P1T, 50-mA, 12-V, 160g"
U1: "IC, Micro-Power 150 mA LDO Regulator"
U2: "IC, Integrated Power Management Unit Top Specification"
X1: "Short jumper"
Y1: "Crystal,"

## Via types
v1: diameter 23.62/23.62/23.62/23.62/23.62/23.62 (per signal layer), hole 11.81, Top to Bottom, 568 vias
v2: diameter 11.81/11.81/11.81/11.81/11.81/11.81 (per signal layer), hole 7.87, Top to Bottom, 63 vias

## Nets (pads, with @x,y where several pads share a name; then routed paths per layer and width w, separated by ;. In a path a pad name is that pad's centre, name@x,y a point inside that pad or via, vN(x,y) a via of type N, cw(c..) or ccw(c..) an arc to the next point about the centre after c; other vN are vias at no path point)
1V5: C17.2 J18.1 J18.2 J30.3 L4.2 U2.H8 | length 3662.6
  Top w7.87: L4.2@100,90 L4.2@125,90 ; L4.2@121.46,186.3 121.46,93.54 L4.2@125,90 ; v1(212.5,56.25) 210,58.75 200,58.75 168.75,90 L4.2@125,90 ; v1(250,56.25) 250.95,57.2 980.31,57.2 J18.1@1035.02,111.91
  Top w8: 60.85,199.23 68.71,207.09 225.76,207.09 264.44,168.41 590.05,168.41 677.81,256.17 1041.26,256.17 1035.02,249.93 J18.2@1035.02,249.7
  Top w9.84: U2.H8@-285.43,191.91 v2(-275.54,182.02)
  Top w30: C17.2@48.99,240.01 48.99,211.09 60.85,199.23 100.04,160.04 100,160 L4.2@100,90
  Inner Layer 3 w4: v2(-275.54,182.02) -275.54,163.72 -257.06,145.24 -118.74,145.24 -112.58,139.08 -112.33,139.33
  Inner Layer 3 w7.87: -112.33,139.33 -59.24,86.25 182.5,86.25 v1(212.5,56.25)
  Bottom w50: v1(212.5,56.25) v1(250,56.25) 250,-72.4 247.48,-74.92 194.51,-127.89 194.51,-387.75 250,-443.24 394.27,-587.51 J30.3@456.25,-587.5
1V8: C8.1 J8.1 J8.2 U2.N6 | length 1181
  Top w7.87: U2.N6@-336.61,63.96 -336.61,34.38 -254.53,-47.71 -234.53,-67.7 -235,-68.17 C8.1@-235,-71.52 -221.16,-71.52 -194.32,-98.36 -194.32,-145.35 -130.49,-209.18 -129.91,-209.76 -129.91,-480.49 -110.4,-500 J8.2@-62.5,-540
  Top w16: C8.1@-221.16,-71.52 -192.07,-71.52 -171.11,-92.48 -171.11,-137.37 -169.13,-137.37 -62.5,-244 J8.1@-62.5,-440
1V35: C13.1 C14.1 J25.1 J25.2 L1.2 U2.B4 | length 2535.4
  Top w7.87: C13.1@-592.89,1294.84 -488.84,1294.84 -467.98,1273.98 C14.1@-467.98,1273.92 -468.24,1273.92 -535.53,1206.63 -535.06,1206.16 v1(-535.06,1153.23) -475.06,1153.23 -424.56,1102.73 L1.2@-424.56,1076.75
  Top w8: C13.1@-592.89,1294.84 -592.89,1347.9 -568.63,1372.16 -568.63,1636.04 -395.51,1809.16 -395.51,2101.85 -324.91,2172.45 -324.91,2274.94 J25.2@-324.85,2275
  Top w9.84: v2(-397.69,355.34) U2.B4@-387.8,345.45
  Inner Layer 3 w12: -398.85,369.8 -397.69,368.64 v2(-397.69,355.34)
  Inner Layer 3 w16: -442.75,423.06 -442.75,413.7 -398.85,369.8
  Inner Layer 3 w20: v1(-535.06,1153.23) -455.36,1153.23 -454.63,1153.96 -337.43,1036.76 -337.43,581.16 -442.75,475.84 -442.75,423.06
2V5: C2.1 J2.1 J2.2 U2.E7 | length 2760.6
  Top w9.84: U2.E7@-311.02,268.68 v2(-301.13,278.57)
  Top w12: v1(-68.85,321.48) -68.85,362.25 C2.1@-68.55,362.55
  Inner Layer 4 w10: v2(-301.13,278.57) -259.42,278.57 -245.48,264.63 -245.35,264.76 -211.18,264.76 -171.87,304.07 -109.39,304.07 -92.97,320.49 -91.98,321.48 v1(-68.85,321.48)
  Inner Layer 4 w12: v1(-68.85,321.48) -58.81,311.47 1.19,311.47 1.19,312.65 108.56,420.02 108.56,520.21 179.68,591.33 389.38,591.33 509.93,470.78 587.02,470.78 623.4,507.16 625.75,507.16 625.75,551.39 705.26,630.9 749.13,630.9 J2.1@750,630.03
  Bottom w8: 154.77,618.75 304.26,618.75 475.48,789.97 617.94,789.97 673.19,734.72 673.19,558.28 701.71,529.76 749.73,529.76 J2.2@750,530.03
  Bottom w10: v1(-68.85,321.48) -7.89,321.48 52.76,382.13 52.76,515.76 154.77,617.77 154.77,618.75
2V5: C7.1 J7.1 J7.2 U2.M2 | length 1209.5
  Top w9.84: v2(-448.87,79.66) U2.M2@-438.98,89.55
  Top w12: C7.1@-526.96,-117.18 -526.96,-90.43 v1(-525.36,-88.83)
  Inner Layer 3 w7.87: v1(-525.36,-88.83) -509.37,-88.83 -509.14,-89.06 -459.25,-39.17 -459.25,34.68 -448.87,45.06 v2(-448.87,79.66)
  Inner Layer 3 w8: v1@-525.36,-98.28 -525.36,-98.67 -549.38,-122.69 -579.77,-122.69 -620.76,-163.68 -620.76,-232.76 -594.97,-258.55 -594.97,-293.8 -595.18,-294.01 -595.18,-528.41 -583.82,-539.77 -522.73,-539.77 J7.2@-522.5,-540
  Inner Layer 3 w16: v1(-525.36,-88.83) -525.36,-98.28 -525.36,-125.68 -559.67,-159.99 -558.74,-160.92 -558.74,-288.01 -522.53,-324.23 J7.1@-522.53,-434.19 ; J7.1@-522.5,-440 J7.1@-522.5,-434.22
2V8: C4.1 J4.1 J4.2 U2.K1 | length 2344.3
  Top w7.87: v2(-478.63,135.84) U2.K1@-464.57,140.73
  Top w12: C4.1@-654.22,-158.63 -654.22,-128.16 v1(-653.82,-127.76)
  Inner Layer 4 w7.87: J4.2@-917.18,-540 -1009.38,-447.8 -1009.38,-56.83 -918.49,34.06 -818.68,34.06 -736.73,-47.89 -737.5,-48.66 -699.56,-48.66 -683.67,-64.55 -683.67,-83.44 -685.13,-84.9 -685.13,-114.42
  Inner Layer 4 w16: -537.8,135.84 v2(-478.63,135.84)
  Inner Layer 4 w25: J4.1@-917.18,-440 -917.18,-317.86 -916.7,-317.38 -956.25,-277.83 -956.25,-75 -956.25,-49.56 -919.53,-12.85 -837.15,-12.85 -762.5,-87.5 -712.05,-87.5 -685.13,-114.42 -672.32,-127.23 -654.35,-127.23 v1(-653.82,-127.76) -653.82,-19.41 -653.02,-18.61 -706.25,34.62 -706.25,131.25 -656.25,181.25 -583.21,181.25 -537.8,135.84
3V: C3.1 J3.1 J3.2 U2.C8 | length 1311.7
  Top w8: U2.C8@-285.43,319.86 -274.96,319.86 -239.84,354.98 C3.1@-198.79,354.98 -179.17,354.98 v1(-169.36,365.3)
  Inner Layer 4 w7.87: v1(-169.36,365.3) -132.37,402.29 -66.76,402.29 31.86,500.91 32.2,500.91 32.2,655.95 70,693.75 J3.2@143.75,693.75
  Inner Layer 4 w16: v1(-169.36,365.3) -171.6,377.74 -187.5,393.64 -187.5,450.71 -187.5,519 -161.41,545.09 -161.41,597.92 34.64,793.97 143.53,793.97 J3.1@143.75,793.75
3V3: C16.2 J17.1 J17.2 L3.2 U2.K2 | length 2958.1
  Top w7.87: J17.1@-1831.25,519.19 -1668.75,519.19 -1212.06,62.5 -1001.5,62.5 C16.2@-996,68 -912,68 -912,69.25 L3.2@-887.5,93.75 -890.35,90.9 v1(-890.35,-73.54)
  Top w8: J17.2@-1831.25,381.4 -1831.1,381.25 -1806.25,381.25 -1768.75,343.75 -1768.75,281.25 -1443.75,-43.75 -1442.59,-42.59 -1106.59,-42.59 C16.2@-996,68
  Top w9.84: v2(-448.87,130.84) U2.K2@-438.98,140.73
  Inner Layer 3 w6: -556.23,8.8 -512.6,52.43 -485.52,79.51 -485.52,94.08 -448.87,130.73 v2(-448.87,130.84)
  Inner Layer 3 w7.87: v1(-890.35,-73.54) -808.01,8.8 -556.23,8.8
3V3: C6.1 J6.1 J6.2 U2.M3 | length 1214.4
  Top w9.84: v2(-423.28,79.66) U2.M3@-413.39,89.55
  Top w12: v1(-464.06,-86.56) -463.87,-86.75 C6.1@-463.87,-117.18
  Inner Layer 3 w7.87: v2(-423.28,79.66) -423.28,25.24 -439.33,9.19 -439.33,-61.83 v1(-464.06,-86.56) -451.91,-86.56 -441.17,-97.3 -441.17,-120.82 -398.51,-163.48 -398.51,-299.11 -314.75,-382.87 -314.75,-530.8 -324.17,-540.22 -324.39,-540 J6.2@-362.5,-540
  Inner Layer 3 w16: v1(-464.06,-86.56) -464.06,-120.3 -465.75,-121.99 -424.26,-163.48 -424.26,-418.3 -401.06,-441.5 -364,-441.5 J6.1@-362.5,-440
+1.8V: C32.2 J19.1 U1.5 | length 888.9
  Top w7.87: v1(43.75,-668.75) v1@43.75,-668.24 ; v1@46.13,-671.75 v1@46.44,-671.44
  Top w16: C32.2@38.19,-629.09 38.19,-662.68 v1@43.75,-668.24 ; v1(43.75,-668.75) v1@46.44,-671.44 ; U1.5@46.13,-713.57 v1@46.13,-671.75
  Inner Layer 4 w25: v1(43.75,-668.75) 171.8,-668.75 380.31,-460.24 508.62,-460.24 559.41,-511.03 556.25,-514.19 J19.1@556.25,-687.5
+3.3V: C31.1 J29.5 J30.1 U1.1 U1.3 | length 662.9
  Top w16: U1.1@46.13,-800.57 46.13,-846.28 58.61,-858.76 106.89,-858.76 120.29,-845.36 120.29,-800.73 U1.3@120.13,-800.57 121.57,-799.13 C31.1@214.95,-799.13 214.32,-799.76 214.32,-834.32 J29.5@300,-920 342.44,-877.56 342.44,-836.13 391.07,-787.5 J30.1@456.25,-787.5
AGND: C1.2 C2.2 C3.2 C4.2 C5.2 C6.2 C7.2 C8.2 C9.2 C10.1 C11.1 C14.2 C15.1 C16.1 C17.1 C18.1 C19.1 C20.1 C21.1 C22.2 C23.2 C24.2 C25.2 C26.2 C27.2 C31.2 C32.1 C33.1 J13.1 J13.2 J14.1 J14.2 J16.3 J16.4 J17.3 J17.4 J18.3 J18.4 J20.3 J21.3 J22.1 J22.2 J23.3 J23.4 J24.1 J24.2 J25.3 J25.4 J26.3 J27.3 J29.6 J31.3 J32.3 J40.1 J41.1 J42.1 J43.1 Q1.1 Q1.2 Q1.3 R3.2 S1.A U1.2 U2.A1 U2.A7 U2.A8 U2.B1 U2.B2 U2.C1 U2.C2 U2.D3 U2.D6 U2.E5 U2.E6 U2.F5 U2.G4 U2.H5 U2.H6 U2.J1 U2.J2 U2.J3 U2.J4 U2.J6 U2.J7 U2.J8 U2.K3 U2.M8 U2.N8 X1.1 | length 13427.7
  Top w7.87: C5.2@-591.12,-157.96 -590.4,-158.68 v1(-590.4,-182.06) ; C7.2@-526.96,-157.18 -526.43,-157.71 v1(-526.43,-182.06) ; v1(-512.68,1587.5) v1(-466.19,1587.5) ; v2(-474.46,380.94) -483.68,371.71 -483.68,363.86 -482.97,363.86 v2(-474.46,355.34) v2@-474.22,355.11 ; C14.2@-467.98,1513.92 -467.98,1585.71 v1(-466.19,1587.5) ; U2.J1@-464.57,166.32 U2.J2@-438.98,166.32 ; C6.2@-463.87,-157.18 -463.87,-173.88 -463.17,-173.88 v1(-458.72,-178.33) v1@-457.6,-179.45 ; v1(-418.7,1587.5) v1(-466.19,1587.5) ; U2.J7@-311.02,166.32 U2.J8@-285.43,166.32 -263.03,166.32 ; U2.M8@-285.43,89.55 U2.N8@-285.43,63.96 ; v2(-275.54,79.66) -267.75,71.87 -267.75,62.14 -269.57,63.96 U2.N8@-285.43,63.96 ; v2(-271.04,61.44) -286.58,61.44 -286.95,65.5 U2.N8@-285.43,63.96 ; v1(-206,175) -170,175 C19.1@-168,173 -154.95,186.05 -151,186.05 v1(-151,205) -186,205 v1(-187,204) ; C23.2@-52.19,566.47 -30.61,566.47 v1(-27.41,563.27)
  Top w9.84: v2(-474.46,156.43) U2.J1@-464.57,166.32 ; v2(-474.46,380.94) U2.A1@-464.57,371.04 ; v2@-474.22,355.11 U2.B1@-464.57,345.45 ; v2(-448.87,156.43) U2.J2@-438.98,166.32 ; v2(-448.87,355.34) U2.B2@-438.98,345.45 ; U2.C2@-439.74,320.63 U2.C2@-438.98,319.86 ; v2(-423.28,130.84) U2.K3@-413.39,140.73 ; v2(-423.28,156.43) U2.J3@-413.39,166.32 ; v2(-397.69,156.43) U2.J4@-387.8,166.32 ; v2(-397.69,227.39) U2.G4@-387.8,217.5 ; U2.H5@-362.2,191.91 v2(-352.31,182.02) ; U2.F5@-362.2,243.09 v2(-352.31,252.98) ; U2.E5@-362.2,268.68 v2(-352.31,278.57) ; U2.J6@-336.61,166.32 v2(-326.72,156.43) ; U2.H6@-336.61,191.91 v2(-326.72,182.02) ; U2.E6@-336.61,268.68 v2(-326.72,278.57) ; U2.D6@-336.61,294.27 v2(-326.72,304.16) ; U2.M8@-285.43,89.55 v2(-275.54,79.66)
  Top w10: U2.C1@-464.57,319.86 U2.C1@-463.8,320.63 ; U2.A7@-311.02,371.04 -303.5,378.57 -292.45,378.57 -285.43,371.55 U2.A8@-285.43,371.04
  Top w11: U2.H5@-362.2,191.91 U2.H6@-336.61,191.91
  Top w12: U2.A1@-464.57,371.04 U2.B1@-464.57,345.45 U2.B2@-438.98,345.45 ; U2.C1@-463.8,320.63 U2.C2@-439.74,320.63 ; U2.C2@-438.98,319.86 -428.48,319.86 -422.89,314.27 -418.82,310.2 -418.82,300.69 -413.39,295.26 U2.D3@-413.39,294.27 ; U2.K3@-413.39,140.73 U2.J3@-413.39,166.32 -404.99,157.92 -399.18,157.92 v2(-397.69,156.43) ; U2.G4@-387.8,217.5 -362.2,217.5 ; U2.H5@-362.2,191.91 -362.2,217.5 ; C9.2@-360.72,-187.94 -328.67,-187.94 v1(-327.9,-188.71) ; U2.J6@-336.61,166.32 U2.H6@-336.61,191.91 ; U2.D6@-336.61,294.27 U2.E6@-336.61,268.68 U2.E5@-362.2,268.68 U2.F5@-362.2,243.09 -362.2,217.5 ; C26.2@-299.14,-111.12 -299.14,-135.2 -289.58,-144.76 v1(-289.58,-145.32) ; -263.03,166.32 -242.59,186.76 -242.59,205.56 -215.83,232.32 -64.92,232.32 v1@-57.36,239.88
  Top w15: U2.A8@-285.43,371.04 -275.41,381.07 -275.41,451.42 -256.06,470.77 -230.83,496 -191.79,496 -191.79,497.08 -176.37,512.5 -176.37,557.19 C21.1@-176.46,557.28
  Top w16: v1(-712.5,587.5) -699.56,587.5 -665.16,553.1 -665.16,493.09 -589.38,417.31 -589.38,416.52 -550.61,416.52 -530.3,396.21 -530.3,375.89 -474.27,319.86 U2.C1@-464.57,319.86 ; C4.2@-654.22,-198.63 -603.65,-198.63 -592.8,-187.78 -592.8,-184.45 v1(-590.4,-182.06) ; v1@-457.6,-179.45 -455.7,-181.35 -401.93,-181.35 C25.2@-401.93,-96.23 ; v1@-57.36,239.88 v1(-53.59,239.88)
  Top w19.68: C2.2@-28.55,362.55 -17.11,362.55 v1(-5.74,373.92)
  Top w20: C16.1@-996,138 -996,185.25 v1(-993.75,187.5) ; C15.1@-748.62,586.75 -747.87,587.5 v1(-712.5,587.5) ; C3.2@-198.79,394.98 -182.21,411.56 -166.32,411.56 v1(-145.77,432.12) ; -176.37,512.5 v1(-143.75,512.5) ; C1.2@-169.39,450.18 -163.71,450.18 -145.77,432.24 v1(-145.77,432.12) ; C22.2@-131.27,394.25 -131.27,418.78 -144.61,432.12 v1(-145.77,432.12) ; v1(-53.59,239.88) -53.46,240.01 C17.1@-21.01,240.01
  Top w25: C11.1@-743.75,977.5 -736.21,1008.5 v1(-735.58,1009.13) ; v1(-637.16,1011.1) -636.21,1010.16 C10.1@-636.21,976.46
  Inner Layer 2 w7.87: -1281.69,1741.56 -1281.34,1741.56 -1236.79,1697.01 -986.96,1697.01 -741.79,1451.84 -741.79,1015.34 v1(-735.58,1009.13) ; J25.4@-600.44,2275 -600.06,2199.78 -413.54,2013.26 -413.54,1763.74 -512.68,1676.44 v1(-512.68,1587.5) ; v2(-474.46,355.34) -475.05,354.75 -520.66,354.75 -536.83,338.58 -536.83,226.76 -496.81,186.74 -429.25,186.74 -423.28,180.77 v2(-423.28,156.43) ; v2(-423.28,130.84) v2(-423.28,156.43) ; v2(-397.69,227.39) -392.38,227.39 -373.91,208.92 -373.91,165.64 -383.12,156.43 v2(-397.69,156.43) v2(-423.28,156.43) ; v2(-326.72,278.57) v2(-326.72,304.16)
  Inner Layer 2 w8: J17.4@-1831.25,105.81 -1046.75,105.81 -992.98,159.58 -992.98,186.73 v1(-993.75,187.5) ; J16.4@-1831.25,749.56 -1816.28,749.56 -1574.14,507.41 -794.41,507.41 -788.3,513.79 -719.44,582.65 -717.35,582.65 v1(-712.5,587.5) ; -1281.69,1741.56 J23.4@-1281.69,2275 ; v1(-53.59,239.88) -55.22,238.25 -56.17,238.25 -56.17,165.94 128.88,-19.11 439.48,-19.11 984.71,526.12 1034.19,526.12 J18.4@1035.02,525.29
  Inner Layer 2 w12: -528.02,156.34 -474.55,156.34 v2(-474.46,156.43) v2(-448.87,156.43)
  Inner Layer 2 w20: v1(-993.75,187.5) -559.18,187.5 -528.02,156.34
  Inner Layer 3 w6: -615.08,205.55 -418.67,205.55 -397.69,226.53 v2(-397.69,227.39)
  Inner Layer 3 w7.87: v1(-993.75,187.5) -831.46,187.5 -813.41,205.55 -615.08,205.55 ; v1(-602.81,123.7) -532.45,123.7 -498.98,157.17 -475.2,157.17 v2(-474.46,156.43)
  Inner Layer 4 w4: v1(-637.16,1011.1) -699.09,1073.04 -700.65,1073.04 -700.65,1260.45 -652.82,1308.28 -342.63,1308.28 -287.96,1253.61 -287.96,1023.98 -356.59,955.35 -356.59,482.55 -383.93,455.21 -383.93,396.42 -366.63,379.12 -366.63,349.06 -360.04,342.47 -346.8,342.47 -339.54,335.21 -339.54,313.27 ; v2(-474.46,380.94) -457.4,397.99 -415.56,397.99 -384.98,367.41 -384.98,331.16 -370.68,316.86 -342.79,316.86 -339.54,313.27 ; v2(-326.72,304.16) -329.09,304.16 -329.59,303.66 -339.54,313.27
  Inner Layer 4 w7.87: v1(-590.4,-182.06) v1(-526.43,-182.06) -522.7,-178.33 v1(-458.72,-178.33) ; v2(-352.31,278.57) v2(-326.72,278.57) ; v1(-327.9,-188.71) -306.72,-188.71 -286.28,-168.27 -286.28,-148.62 v1(-289.58,-145.32)
  Inner Layer 5 w12: v1(-5.74,373.92) 19.11,349.06 323.29,349.06 338.48,364.25 379.5,364.25 v1(381.25,362.5)
  Inner Layer 5 w22: v1(381.25,462.5) 424.91,462.5 424.91,514.01 423.4,512.5 v1(381.25,512.5)
  other v1: -1768.75,-1312.5 -1718.75,-1312.5 -1668.75,-1312.5 -1618.75,-1312.5 225,-1287.5 275,-1287.5 325,-1287.5 375,-1287.5 425,-1287.5 475,-1287.5 525,-1287.5 575,-1287.5 625,-1287.5 675,-1287.5 725,-1287.5 775,-1287.5 1106.25,-1281.25 1156.25,-1281.25 1206.25,-1281.25 -737.5,-1275 -687.5,-1275 -1768.75,-1262.5 -1718.75,-1262.5 -1668.75,-1262.5 -1618.75,-1262.5 225,-1237.5 275,-1237.5 325,-1237.5 375,-1237.5 425,-1237.5 475,-1237.5 525,-1237.5 575,-1237.5 625,-1237.5 675,-1237.5 725,-1237.5 775,-1237.5 1106.25,-1231.25 1156.25,-1231.25 1206.25,-1231.25 -787.5,-1225 -737.5,-1225 -687.5,-1225 -637.5,-1225 225,-1187.5 275,-1187.5 325,-1187.5 375,-1187.5 425,-1187.5 475,-1187.5 525,-1187.5 575,-1187.5 625,-1187.5 675,-1187.5 725,-1187.5 775,-1187.5 1106.25,-1181.25 1156.25,-1181.25 1206.25,-1181.25 1550,-1006.25 1600,-1006.25 1650,-1006.25 1550,-956.25 1600,-956.25 1650,-956.25 1550,-906.25 1600,-906.25 1650,-906.25 -345.48,-871.59 -215.29,-871.59 -345.48,-821.59 -215.29,-821.59 1325,-800 1375,-800 1425,-800 1325,-750 1375,-750 1425,-750 -368.75,-731.25 -218.75,-731.25 1325,-700 1375,-700 1425,-700 -368.75,-681.25 -218.75,-681.25 -2118.75,-487.5 -2068.75,-487.5 -2118.75,-437.5 -2068.75,-437.5 -2118.75,-387.5 -2068.75,-387.5 -2118.75,-281.25 -2068.75,-281.25 -1575,-281.25 -1525,-281.25 -2118.75,-231.25 -2068.75,-231.25 -1575,-231.25 -1525,-231.25 -206.55,-182.06 -2118.75,-181.25 -2068.75,-181.25 -1575,-181.25 -1525,-181.25 -1575,-125 -1525,-125 2.31,-92.1 46.06,-92.1 -1575,-75 -1525,-75 -2112.5,-62.5 -2062.5,-62.5 -1575,-25 -1525,-25 -2112.5,-12.5 -2062.5,-12.5 -2112.5,37.5 -2062.5,37.5 1543.75,50 1593.75,50 1643.75,50 -618.75,93.75 1543.75,100 1593.75,100 1643.75,100 -636.27,123.7 -2112.5,137.5 -2062.5,137.5 1543.75,150 1593.75,150 1643.75,150 -2112.5,187.5 -2062.5,187.5 1543.75,206.25 1593.75,206.25 1643.75,206.25 381.25,212.5 -2112.5,237.5 -2062.5,237.5 1543.75,256.25 1593.75,256.25 1643.75,256.25 381.25,262.5 1543.75,306.25 1593.75,306.25 1643.75,306.25 381.25,312.5 -1318.75,362.5 1543.75,362.5 1593.75,362.5 1643.75,362.5 -2112.5,375 -2062.5,375 -636.27,378.47 -602.81,378.47 -569.34,378.47 -1281.25,393.75 -1356.25,400 381.25,412.5 1543.75,412.5 1593.75,412.5 1643.75,412.5 -2112.5,425 -2062.5,425 -1318.75,431.25 -1393.75,437.5 1543.75,462.5 1593.75,462.5 1643.75,462.5 -2112.5,475 -2062.5,475 -1431.25,479 -1387.5,479 -1340,479 1593.75,518.75 1643.75,518.75 -1487.5,540 -1431.25,540 -1375,540 381.25,562.5 1643.75,568.75 -1543.75,587.5 -1487.5,587.5 -1431.25,587.5 -1375,587.5 -27.41,598.45 -2118.75,618.75 -2068.75,618.75 -623.65,621.67 -589.6,621.67 -1543.75,643.75 -1487.5,643.75 -1431.25,643.75 -1375,643.75 -2118.75,668.75 -2068.75,668.75 -1600,700 -1543.75,700 -1487.5,700 -1431.25,700 -1375,700 -259.65,700.35 -2118.75,718.75 -2068.75,718.75 -259.65,737.07 -1487.5,756.25 -1431.25,756.25 -1375,756.25 -259.65,772.35 -2118.75,906.25 -2068.75,906.25 -2118.75,956.25 -2068.75,956.25 924.61,959.92 962.01,959.92 999.41,959.92 -2118.75,1006.25 -2068.75,1006.25 -1206.25,1168.75 -1156.25,1168.75 -1100,1168.75 -1050,1168.75 -2125,1175 -2075,1175 -1206.25,1218.75 -1156.25,1218.75 -1100,1218.75 -1050,1218.75 -2125,1225 -2075,1225 -1206.25,1268.75 -1156.25,1268.75 -1100,1268.75 -1050,1268.75 -2125,1275 -2075,1275 -1318.75,1318.75 -1268.75,1318.75 -1206.25,1318.75 -1156.25,1318.75 -1100,1318.75 -1050,1318.75 -1318.75,1368.75 -1268.75,1368.75 -1206.25,1368.75 -1156.25,1368.75 -1100,1368.75 -1050,1368.75 243.75,1406.25 293.75,1406.25 343.75,1406.25 393.75,1406.25 443.75,1406.25 493.75,1406.25 556.25,1406.25 606.25,1406.25 656.25,1406.25 706.25,1406.25 -1318.75,1418.75 -1268.75,1418.75 -1206.25,1418.75 -1156.25,1418.75 -1100,1418.75 -1050,1418.75 243.75,1456.25 293.75,1456.25 343.75,1456.25 393.75,1456.25 443.75,1456.25 493.75,1456.25 556.25,1456.25 606.25,1456.25 656.25,1456.25 706.25,1456.25 -1518.75,1468.75 -1468.75,1468.75 -1418.75,1468.75 -1368.75,1468.75 -1318.75,1468.75 -1268.75,1468.75 -1206.25,1468.75 -1156.25,1468.75 -1100,1468.75 -1050,1468.75 -668.75,1487.5 -618.75,1487.5 243.75,1506.25 293.75,1506.25 343.75,1506.25 393.75,1506.25 443.75,1506.25 493.75,1506.25 556.25,1506.25 606.25,1506.25 656.25,1506.25 706.25,1506.25 -1518.75,1518.75 -1468.75,1518.75 -1418.75,1518.75 -1368.75,1518.75 -1318.75,1518.75 -1268.75,1518.75 -1206.25,1518.75 -1156.25,1518.75 -1100,1518.75 -1050,1518.75 -668.75,1537.5 -618.75,1537.5 243.75,1562.5 293.75,1562.5 343.75,1562.5 393.75,1562.5 443.75,1562.5 493.75,1562.5 556.25,1562.5 606.25,1562.5 656.25,1562.5 706.25,1562.5 -1518.75,1568.75 -1468.75,1568.75 -1418.75,1568.75 -1368.75,1568.75 -1318.75,1568.75 -1268.75,1568.75 -1206.25,1568.75 -1156.25,1568.75 -1100,1568.75 -1050,1568.75 -668.75,1587.5 -618.75,1587.5 243.75,1612.5 293.75,1612.5 343.75,1612.5 393.75,1612.5 443.75,1612.5 493.75,1612.5 556.25,1612.5 606.25,1612.5 656.25,1612.5 706.25,1612.5 243.75,1662.5 293.75,1662.5 343.75,1662.5 393.75,1662.5 443.75,1662.5 493.75,1662.5 556.25,1662.5 606.25,1662.5 656.25,1662.5 706.25,1662.5 243.75,1718.75 293.75,1718.75 343.75,1718.75 393.75,1718.75 443.75,1718.75 493.75,1718.75 556.25,1718.75 606.25,1718.75 656.25,1718.75 706.25,1718.75 243.75,1768.75 293.75,1768.75 343.75,1768.75 393.75,1768.75 443.75,1768.75 493.75,1768.75 556.25,1768.75 606.25,1768.75 656.25,1768.75 706.25,1768.75 -1231.25,1775 -1181.25,1775 -1125,1775 -1075,1775 243.75,1818.75 293.75,1818.75 343.75,1818.75 393.75,1818.75 443.75,1818.75 493.75,1818.75 556.25,1818.75 606.25,1818.75 656.25,1818.75 706.25,1818.75 -1231.25,1825 -1181.25,1825 -1125,1825 -1075,1825 -1231.25,1875 -1181.25,1875 -1125,1875 -1075,1875 243.75,1875 293.75,1875 343.75,1875 393.75,1875 443.75,1875 493.75,1875 556.25,1875 606.25,1875 656.25,1875 706.25,1875 -2006.25,1893.75 -1956.25,1893.75 -1893.75,1893.75 -1843.75,1893.75 -681.25,1906.25 -631.25,1906.25 -575,1906.25 -525,1906.25 243.75,1925 293.75,1925 343.75,1925 393.75,1925 443.75,1925 493.75,1925 556.25,1925 606.25,1925 656.25,1925 706.25,1925 -1231.25,1931.25 -1181.25,1931.25 -1125,1931.25 -1075,1931.25 -2006.25,1943.75 -1956.25,1943.75 -1893.75,1943.75 -1843.75,1943.75 -681.25,1956.25 -631.25,1956.25 -575,1956.25 -525,1956.25 243.75,1975 293.75,1975 343.75,1975 393.75,1975 443.75,1975 493.75,1975 556.25,1975 606.25,1975 656.25,1975 706.25,1975 -1231.25,1981.25 -1181.25,1981.25 -1125,1981.25 -1075,1981.25 -2006.25,1993.75 -1956.25,1993.75 -1893.75,1993.75 -1843.75,1993.75 -681.25,2006.25 -631.25,2006.25 -575,2006.25 -525,2006.25 -1231.25,2031.25 -1181.25,2031.25 -1125,2031.25 -1075,2031.25 731.25,2350 781.25,2350 831.25,2350 881.25,2350 931.25,2350 981.25,2350 731.25,2400 781.25,2400 831.25,2400 881.25,2400 931.25,2400 981.25,2400 731.25,2450 781.25,2450 831.25,2450 881.25,2450 931.25,2450 981.25,2450
AGND_XTAL: C28.2 C29.2 C30.1 U2.G7 X1.2 | length 988.3
  Top w0.5: v1(229,390.53) 238.72,380.81 238.72,379.7
  Top w7.87: C28.2@163.29,414.17 164.08,414.17 C28.2@168.52,409.72 ; C29.2@163.29,535.71 169.42,529.58 168.52,528.68 C29.2@168.52,524.88
  Top w9.84: U2.G7@-311.02,217.5 v2(-301.13,227.39)
  Top w19.68: C30.1@-157.97,261.32 -136.32,261.32 v1(-136.32,262.11)
  Inner Layer 5 w7.87: v1(193.31,544.07) 193.31,506.33 v1(193.31,505.69) ; v1(229,390.53) v1(193.31,390.53) v1(193.31,428.92) ; v1(229,428.92) v1(193.31,428.92) ; v1(229,544.07) v1(229,505.69) v1(193.31,505.69) ; v1(193.31,428.92) v1(193.31,505.69)
  Inner Layer 5 w12: v2(-301.13,227.39) -230.88,227.39 -194,264.27 -138.48,264.27 v1(-136.32,262.11) -136.32,322.71 -41.19,417.84 165.43,417.84 178.94,431.35 190.87,431.35 v1(193.31,428.92)
EN1: J43.2 R18.1 U2.M7 | length 2301.6
  Top w7.87: U2.M7@-311.02,89.55 -302.66,81.18 -302.59,79.66 v2(-301.13,79.66)
  Top w8: J43.2@740.27,-368.32 740.37,-368.32 788.19,-416.14 1172.12,-416.14 1186.89,-430.91 1186.89,-622.85 1186.43,-622.85 1075,-734.28 R18.1@1075,-792.5
  Bottom w6: v2(-301.13,79.66) -264.87,115.92 -247.98,115.92
  Bottom w8: -247.98,115.92 -231.41,132.49 272.37,132.49 344.99,59.87 344.99,-95.26 451.51,-201.78 616.36,-201.78 674.15,-259.57 674.15,-335.49 706.74,-368.08 740.03,-368.08 J43.2@740.27,-368.32
EN1_S: Q4.2 R18.2 R21.1 | length 180.3
  Top w8: Q4.2@896.25,-831.25 1003.75,-831.25 R21.1@1006.25,-833.75 1073.75,-833.75 R18.2@1075,-832.5
EN2: J40.2 R17.1 U2.M6 | length 2885.7
  Top w7.87: U2.M6@-336.61,89.55 v2(-326.72,79.66)
  Top w8: R17.1@1075,-986.25 1075,-922.1 1209.7,-787.4 1209.7,-404.38 1174.07,-368.75 J40.2@1131.25,-368.75
  Bottom w6: v2(-326.72,79.66) -296.9,110.41 -272.83,134.48 -253.96,134.48 -240.15,148.29 -240.15,150
  Bottom w7.87: -240.15,150 293.75,150 375,68.75 375,-81.25 468.75,-175 1231.25,-175 1275,-218.75 1275,-325 1231.25,-368.75 J40.2@1131.25,-368.75
EN2_S: Q3.2 R17.2 R22.1 | length 180.3
  Top w8: Q3.2@896.25,-1025 1003.75,-1025 R22.1@1006.25,-1027.5 1073.75,-1027.5 R17.2@1075,-1026.25
LDO2: C9.1 J9.1 J9.2 U2.N4 | length 1342.8
  Top w7.87: C9.1@-360.72,-147.94 -330.34,-147.94 v1(-330.07,-148.21)
  Top w12: -387.8,-7.35 U2.N4@-387.8,63.96
  Top w16: -387.8,-7.35 -360.72,-34.43 C9.1@-360.72,-147.94
  Inner Layer 3 w7.87: v1@-330.07,-137.88 -302.59,-110.4 -302.59,-108.96 -286.41,-108.96 -277.53,-117.84 -259.57,-135.8 -259.57,-492.93 J9.2@-212.5,-540
  Inner Layer 3 w16: v1(-330.07,-148.21) -330.07,-137.88 -330.07,-93.74 -319.94,-83.61 -232.32,-83.61 -218.45,-97.48 -218.29,-97.32 -152.9,-162.71 -152.9,-301.9 -212.6,-361.6 -212.5,-361.7 J9.1@-212.5,-440
LDO8: C5.1 J5.1 J5.2 U2.M1 | length 1526.9
  Top w7.87: -492.86,8.29 -492.86,69.56 -472.88,89.55 U2.M1@-464.57,89.55
  Top w10: v1(-570.15,-91.68) -570.15,-68.16 -493.7,8.29 -492.86,8.29
  Top w12: C5.1@-591.12,-117.96 -591.12,-106.14 -576.66,-91.68 v1(-570.15,-91.68)
  Inner Layer 3 w7.87: J5.1@-677.5,-437.5 J5.1@-672.5,-440
  Inner Layer 3 w8: J5.2@-672.5,-540 -728.5,-540 -761.6,-506.9 -764.25,-506.9 -764.25,-113.35 -708.48,-57.58 -602.72,-57.58 -599.79,-57.58 -570.15,-87.22 v1(-570.15,-91.68)
  Inner Layer 3 w16: J5.1@-677.5,-437.5 -679.66,-439.66 -698.47,-439.66 -725.61,-412.52 -728.5,-412.52 -728.5,-131.1 -689.89,-92.49 -570.96,-92.49 v1(-570.15,-91.68)
NetC10_2: C10.2 C11.2 J23.1 J23.2 Q2.5 | length 3681.6
  Top w7.87: J23.1@-868.31,2275 -867.62,2274.31 -867.62,2254.95 -846.76,2234.09 -846.76,952.67 v1(-819.86,925.77) -819.72,925.77 -797.22,903.27 v1(-797.22,895.15) ; v1(-819.86,862.5) -797.22,885.14 -797.22,892.42 -792.14,897.5 C11.2@-743.75,897.5 -741.25,897.5 -741.25,893.75 -739.85,895.15 v1(-691.37,895.15) -690.06,896.46 C10.2@-636.21,896.46 ; C10.2@-636.56,890.31 C10.2@-639.99,893.74 ; v1(-475,795) v1(-435.32,795) ; Q2.5@-433.59,730.51 -433.59,732.81 -435.32,734.54 v1(-435.32,795) ; v1(-395,795) v1(-435.32,795) ; C10.2@-639.99,893.74 -643.75,897.5 -637.25,897.5 C10.2@-636.21,896.46 ; C10.2@-639.99,893.74 -637.27,896.46 C10.2@-636.21,896.46
  Top w8: J23.2@-1006.1,2275 -1006.1,2338.1 -1008,2340 -971,2377 -822,2377 -744,2299 -744,1224 -575,1055 -575,921.41 -599.83,896.58 -636.09,896.58 C10.2@-636.21,896.46
  Inner Layer 3 w7.87: v1(-475,795) v1@-475,795.11
NetC12_1: C12.1 L1.1 Q1.5 Q2.1 Q2.2 Q2.3 U2.A4 | length 1532
  Top w7.87: v1@-531.34,588.11 -531.25,588.02 v1(-531.25,592.07) ; Q2.3@-515.28,717.71 Q2.2@-515.28,743.31 Q2.1@-515.28,768.9 -515.28,870.44 -466.45,919.27 L1.1@-424.56,919.27 ; U2.A4@-387.8,371.04 -387.8,595.71 v1(-418.77,626.68) -387.85,626.68 -334.15,680.38 -334.15,813.13 -423.38,902.36 -423.38,918.09 L1.1@-424.56,919.27 ; Q1.5@-138.43,730.51 -138.43,866.18 -138.3,866.31 -191.26,919.27 L1.1@-424.56,919.27
  Top w16: C12.1@-531.34,546.47 v1@-531.34,588.11
  Inner Layer 3 w16: v1(-531.25,592.07) -496.67,626.65 v1@-418.8,626.65
NetC12_2: C12.2 U2.A2 | length 150.6
  Top w16: C12.2@-531.34,466.47 -532.06,465.75 -532.06,452.06 -489.99,409.99 -462.19,409.99 -438.98,386.78 U2.A2@-438.98,371.04
NetC13_2: C13.2 U2.C5 | length 1105.6
  Top w9.84: U2.C5@-362.2,319.86 v2(-352.31,329.75)
  Top w16: v1(-633.05,1255.18) -633.05,1294.68 C13.2@-632.89,1294.84
  Inner Layer 4 w4: -413.96,411.62 -375.63,373.29 -375.63,336.34 -369.04,329.75 v2(-352.31,329.75)
  Inner Layer 4 w8: v1(-633.05,1255.18) -633.46,1254.77 -633.46,1092.55 -568.35,1027.44 -568.35,762.95 -469.1,663.7 -469.1,466.76 -413.96,411.62
NetC27_1: C27.1 J27.1 | length 272.5
  Top w19.68: J27.1@737.5,1205 812.5,1205 925,1317.5 960.24,1317.5 C27.1@962.5,1315.24
NetC28_1: C28.1 R4.1 Y1.2 | length 169.8
  Top w7.87: R4.1@-32.2,431.21 6.22,431.21 27.95,409.48 47.62,409.48 Y1.2@47.8,409.66 47.86,409.72 C28.1@128.52,409.72
NetC29_1: C29.1 R5.1 Y1.1 | length 176.1
  Top w7.87: R5.1@-32.2,493.71 0.39,493.71 34.27,527.59 Y1.1@47.62,527.59 ; Y1.1@47.8,527.77 Y1.1@47.62,527.59 ; C29.1@128.52,524.88 50.32,524.88 Y1.1@47.62,527.59
NetC30_2: C30.2 J28.1 U2.G8 | length 487.9
  Top w10: U2.G8@-285.43,217.5 -263.52,217.5 -219.19,261.83 -198.48,261.83 C30.2@-197.97,261.32
  Top w11.81: C30.2@-197.97,261.32 -197.97,267.13 -166.7,298.4 -9.45,298.4 11.01,318.86 105.57,318.86 135,289.43 J28.1@135,280
NetC33_2: C33.2 J27.2 U2.D7 | length 1741.9
  Top w8: C33.2@637.5,1045 637.5,1084.43 658.07,1105 J27.2@737.5,1105
  Top w9.84: U2.D7@-311.02,294.27 v2(-301.13,304.16)
  Inner Layer 4 w7.87: v1(442.81,684.82) 442.81,810.31 J27.2@737.5,1105
  Bottom w10: v2(-301.13,304.16) -283.88,304.16 -234.01,254.29 -200.28,254.29 -155.36,299.21 -112.26,299.21 -95.23,282.18 -40.72,282.18 -3.5,282.18 92.17,377.85 92.17,513.74 168.33,589.9 168.33,591.73 328.65,591.73 421.73,684.81 v1(442.81,684.82)
NetJ10_1: J10.1 U2.C6 | length 2564
  Top w9.84: U2.C6@-336.61,319.86 v2(-326.72,329.75)
  Inner Layer 4 w3.94: v2(-326.72,329.75) -313.93,316.96 -280.12,316.96
  Inner Layer 4 w7.87: -280.12,316.96 -254.53,316.96 -246.28,325.21 -206.31,325.21 -202.42,321.32 -130.25,321.32 -97.43,354.14 -45.07,354.14 -29.88,338.95 -3.29,338.95 84.52,426.76 85.34,426.76 85.34,541.59 154.35,610.6 451.9,610.6 481.43,581.07 581.22,581.07 866.48,866.33 866.48,1729.95 903.81,1767.28 J10.1@1003.8,1767.28
NetJ11_1: J11.1 U2.D5 | length 2855
  Top w9.84: U2.D5@-362.2,294.27 v2(-352.31,304.16)
  Inner Layer 4 w4: v2(-352.31,304.16) -353.85,305.7 -362.99,305.7 -374.5,294.19 -374.5,236.16 -349.63,211.29 -250.2,211.29 -212.64,211.29 -195.84,228.09 -129.04,228.09 -122,221.05
  Inner Layer 4 w7.87: 85.67,152.44 481.16,152.44 576.52,247.8 576.52,304.48 564.04,316.96 v1(545.18,316.96)
  Inner Layer 4 w8: -122,221.05 -94.9,193.95 44.16,193.95 85.67,152.44
  Bottom w7.87: v1(545.18,316.96) 729.73,316.96 889.22,476.45 889.22,663.85 1048.72,823.35 1048.72,1427.75 1003.95,1472.52 1003.95,1604.63 J11.1@1003.8,1604.78
NetJ12_1: J12.1 U2.C4 | length 2103.4
  Top w9.84: v2(-397.69,329.75) U2.C4@-387.8,319.86
  Inner Layer 3 w7.87: J12.1@-1802.04,1482.46 -1725.62,1482.46 -1216.38,973.22 -1216.38,643.75 -1012.13,439.5 -570.48,439.5 -527.79,396.81 -527.79,371.89 -485.65,329.75 v2(-397.69,329.75)
NetJ20_2: J20.2 U2.N1 | length 1931.3
  Top w9.84: v2(-474.46,54.06) U2.N1@-464.57,63.96
  Bottom w7.87: -549.08,130.95 -474.46,56.33 v2(-474.46,54.06) ; 39.07,681.88 98.27,741.08 98.27,742.22 216.57,742.22 365.66,891.31 365.66,1054.18 317.04,1102.8 J20.2@279.4,1102.8
  Bottom w8: -549.08,130.95 -549.08,359.26 -498.04,410.3 -411.49,410.3 -376.79,375.6 -316.92,375.6 -292.4,400.12 -291.31,400.12 -151.99,400.12 -128.28,376.41 -48.37,376.41 10.83,435.61 10.83,515.76 39.07,544 39.07,681.88
NetJ21_2: J21.2 U2.N2 | length 1347.7
  Top w7.87: -438.98,52.97 U2.N2@-438.98,63.96
  Top w10: v1(-503.61,-40.61) -469.63,-6.63 -469.3,-6.63 -469.3,23.49 -438.98,52.97
  Inner Layer 3 w7.87: J21.2@-1118.75,-713.75 -1119.89,-712.61 -1203.67,-712.61 -1233.87,-682.41 -1233.87,-543.39 -719.85,-29.37 -719.85,-28.68 -579.81,-28.68 -567.88,-40.61 v1(-503.61,-40.61)
NetJ26_2: J26.2 U2.L6 | length 2789.3
  Top w9.84: U2.L6@-336.61,115.14 v2(-326.72,105.25)
  Inner Layer 3 w4: -339.48,65.79 -339.48,92.49 v2(-326.72,105.25)
  Inner Layer 3 w7.87: -43.46,-22.22 -38.64,-22.22 4.05,-64.91 1209.42,-64.91 1287.98,13.65 1287.98,671.49 1458.19,842.18 1557.77,842.18 J26.2@1559.03,843.44
  Inner Layer 3 w8: -339.48,65.79 -339.48,38.11 -279.15,-22.22 -43.46,-22.22
NetJ29_1: J29.1 Q4.3 | length 315
  Top w8: J29.1@500,-920 742.5,-920 Q4.3@793.75,-868.75
NetJ29_2: J29.2 Q3.3 | length 311.4
  Top w8: J29.2@500,-1020 751.25,-1020 Q3.3@793.75,-1062.5
NetJ29_9: J29.9 Q6.3 | length 873.6
  Top w12: v1(306.18,-397.85) 305.75,-398.28 305.75,-413.83 Q6.3@326.68,-434.76
  Inner Layer 4 w16: J29.9@100,-920 29.3,-920 29.17,-920.13 -39.53,-851.43 -39.95,-851.43 -39.95,-637.49 199.69,-397.85 v1(306.18,-397.85)
NetJ29_10: J29.10 Q5.3 | length 1358.1
  Top w12: v1(279.44,-241.02) 295.83,-224.63 Q5.3@325.24,-224.63
  Inner Layer 4 w16: J29.10@100,-1020 99.24,-1019.24 -20,-1019.24 -134.95,-904.29 -134.95,-336.8 -135.35,-336.4 -82.43,-283.48 237.42,-283.48 237.42,-283.04 v1(279.44,-241.02)
NetJ31_2: J31.2 U2.F1 | length 3899.6
  Top w7.87: U2.F1@-464.57,243.09 -464.57,242.57 v2(-458.5,236.5)
  Inner Layer 4 w8: v2(-458.5,236.5) -450.26,236.5 -446.29,232.53 -446.29,202.57 -469.5,179.36 -503,179.36 -555.95,232.31 -555.95,296.15 -602.5,342.7 -1232.49,342.7 -1469.53,105.66 -1469.53,-1216.11 -1393.98,-1291.66 -839.58,-1291.66 -815.69,-1315.55 -480.04,-1315.55 -480.04,-1315.43 J31.2@-297.57,-1132.96
NetJ32_1: J32.1 R6.2 | length 90
  Top w7.87: R6.2@455,730 J32.1@545,730
NetJ32_2: J32.2 U2.J5 | length 1538.1
  Top w9.84: U2.J5@-362.2,166.32 v2(-352.31,156.43)
  Inner Layer 3 w4: v2(-352.31,156.43) -332.28,136.39 -315.83,136.39 -287.76,108.32 -265.66,108.32 -240.33,82.99 -240.33,39.5 -225.13,24.3
  Inner Layer 3 w7.87: 419.46,14.33 462.01,56.88 v1(462.01,393.73)
  Inner Layer 3 w8: -225.13,24.3 73.23,24.3 83.59,13.94 419.07,13.94 419.46,14.33
  Bottom w7.87: v1(462.01,393.73) 462.01,547.01 J32.2@545,630
NetJ33_1: J33.1 R8.2 | length 115
  Top w19.68: J33.1@1374,1098.3 R8.2@1489,1098.3
NetJ33_2: J33.2 U2.L5 | length 2911.2
  Top w9.84: U2.L5@-362.2,115.14 v2(-352.31,105.25)
  Inner Layer 4 w4: v2(-352.31,105.25) -328.62,128.94 -297.33,128.94 -255.4,87.01 -255.4,39.65 -249.53,33.78 -249.53,33.22
  Inner Layer 4 w7.87: 1254.89,963.26 1274.91,983.28 1274.91,1097.39 J33.2@1274,1098.3
  Inner Layer 4 w8: -249.53,33.22 -219.6,3.29 -97.87,3.29 -73.96,27.21 95.25,27.21 217.22,-94.76 407.58,-94.76 451.01,-51.33 1190.87,-51.33 1255.4,13.2 1255.72,13.2 1255.72,962.43 1254.89,963.26
NetJ33_3: J33.3 R9.2 | length 115
  Top w19.68: J33.3@1374,1198.3 R9.2@1489,1198.3
NetJ33_4: J33.4 U2.F6 | length 2379.8
  Top w9.84: U2.F6@-336.61,243.09 v2(-326.72,252.98)
  Inner Layer 4 w3.94: v2(-326.72,252.98) -313.93,240.19 -260.13,240.19
  Inner Layer 4 w7.87: -260.13,240.19 -204.79,240.19 -204.72,240.12 -157.2,287.64 -111.04,287.64 -101.18,277.78 -11.17,277.78 86.85,179.76 397.6,179.76 493.21,275.37 v1(545.18,275.37)
  Bottom w7.87: v1(545.18,275.37) 740.92,275.37 919.54,453.99 919.54,647.06 1096.29,823.81 1096.29,1097.56 1197.02,1198.29 J33.4@1274,1198.3
NetJ33_5: J33.5 R10.2 | length 115
  Top w19.68: J33.5@1374,1298.3 R10.2@1489,1298.3
NetJ33_6: J33.6 U2.L2 | length 4245.9
  Top w9.84: v2(-448.87,105.25) U2.L2@-438.98,115.14
  Inner Layer 3 w7.87: J33.6@1274,1298.3 1325.88,1246.42 1420.67,1246.42 1442.37,1224.72 v1(1442.37,1147.81)
  Inner Layer 4 w7.87: v2(-448.87,105.25) -449.15,105.53 -483.36,105.53 -506.61,82.28 -506.61,26.07 -496.36,15.82 -410.95,15.82 -383.96,-11.17 -282.3,-11.17 -240.61,-52.86 64.56,-52.86 182.62,-170.92 183.12,-170.42 330.55,-170.42 414.64,-254.51 582.51,-254.51 656.59,-328.59 656.59,-513.2 657.55,-513.2 695.18,-550.83 1161.96,-550.83 1350.12,-362.67 1350.12,917.37 1348.22,919.27 1442.32,1013.37 1442.32,1147.76 v1(1442.37,1147.81)
NetJ33_7: J33.7 R11.2 | length 115
  Top w19.68: J33.7@1374,1398.3 R11.2@1489,1398.3
NetJ33_8: J33.8 U2.B7 | length 3874.8
  Top w9.84: U2.B7@-311.02,345.45 v2(-301.13,355.34)
  Inner Layer 4 w7.87: v2(-301.13,355.34) -285.14,339.35 -257.73,339.35 -248.01,349.07 -202.7,349.07 -191.97,338.34 -149.03,338.34 -110.82,376.55 -58.08,376.55 64.84,499.47 67.93,499.47 67.93,550.27 67.13,551.07 159.81,643.75 459.69,643.75 497.19,681.25 497.19,760.41 632.89,896.11 748.71,896.11 836.57,983.97 836.57,2153.86 895.33,2212.62 1074.25,2212.62 1113.69,2173.18 1113.69,1502.24 1145.51,1470.42 1145.51,1469.44 1216.06,1398.9 1216.06,1398.3 J33.8@1274,1398.3
NetJ33_9: J33.9 R12.2 | length 115
  Top w19.68: J33.9@1374,1498.3 R12.2@1489,1498.3
NetJ33_10: J33.10 U2.H7 | length 3750.9
  Top w9.84: U2.H7@-311.02,191.91 v2(-301.13,182.02)
  Inner Layer 4 w4: v2(-301.13,182.02) -301.13,148.1 -244.82,91.79 -244.82,53.95 -239.27,48.39
  Inner Layer 4 w7.87: -239.27,48.39 -212.52,21.65 -116.98,21.65 -116.89,21.56 -87.31,51.14 109.27,51.14 228.23,-67.82 390.72,-67.82 429.16,-29.38 1184.32,-29.38 1226.32,12.62 1226.32,872.87 1148.8,950.39 1146.71,950.39 1146.71,1192.36 1200.07,1245.72 1411.84,1245.72 1453.82,1287.7 1453.82,1517.61 1426.58,1544.85 1311.55,1544.85 1274,1507.3 J33.10@1274,1498.3
NetJ33_11: J33.11 R13.2 | length 115
  Top w19.68: J33.11@1374,1598.3 R13.2@1489,1598.3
